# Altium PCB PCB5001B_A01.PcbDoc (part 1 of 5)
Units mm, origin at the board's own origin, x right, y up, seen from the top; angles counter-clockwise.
Board outline 115 x 60 mm, 6 copper layers (Top Layer, GND Layer 2, Signal Layer 3, Signal Layer 4, VCC Layer 5, Bottom Layer), stack 1.555 mm thick; 370 components, 274 nets, 1305 pads, 1129 vias.
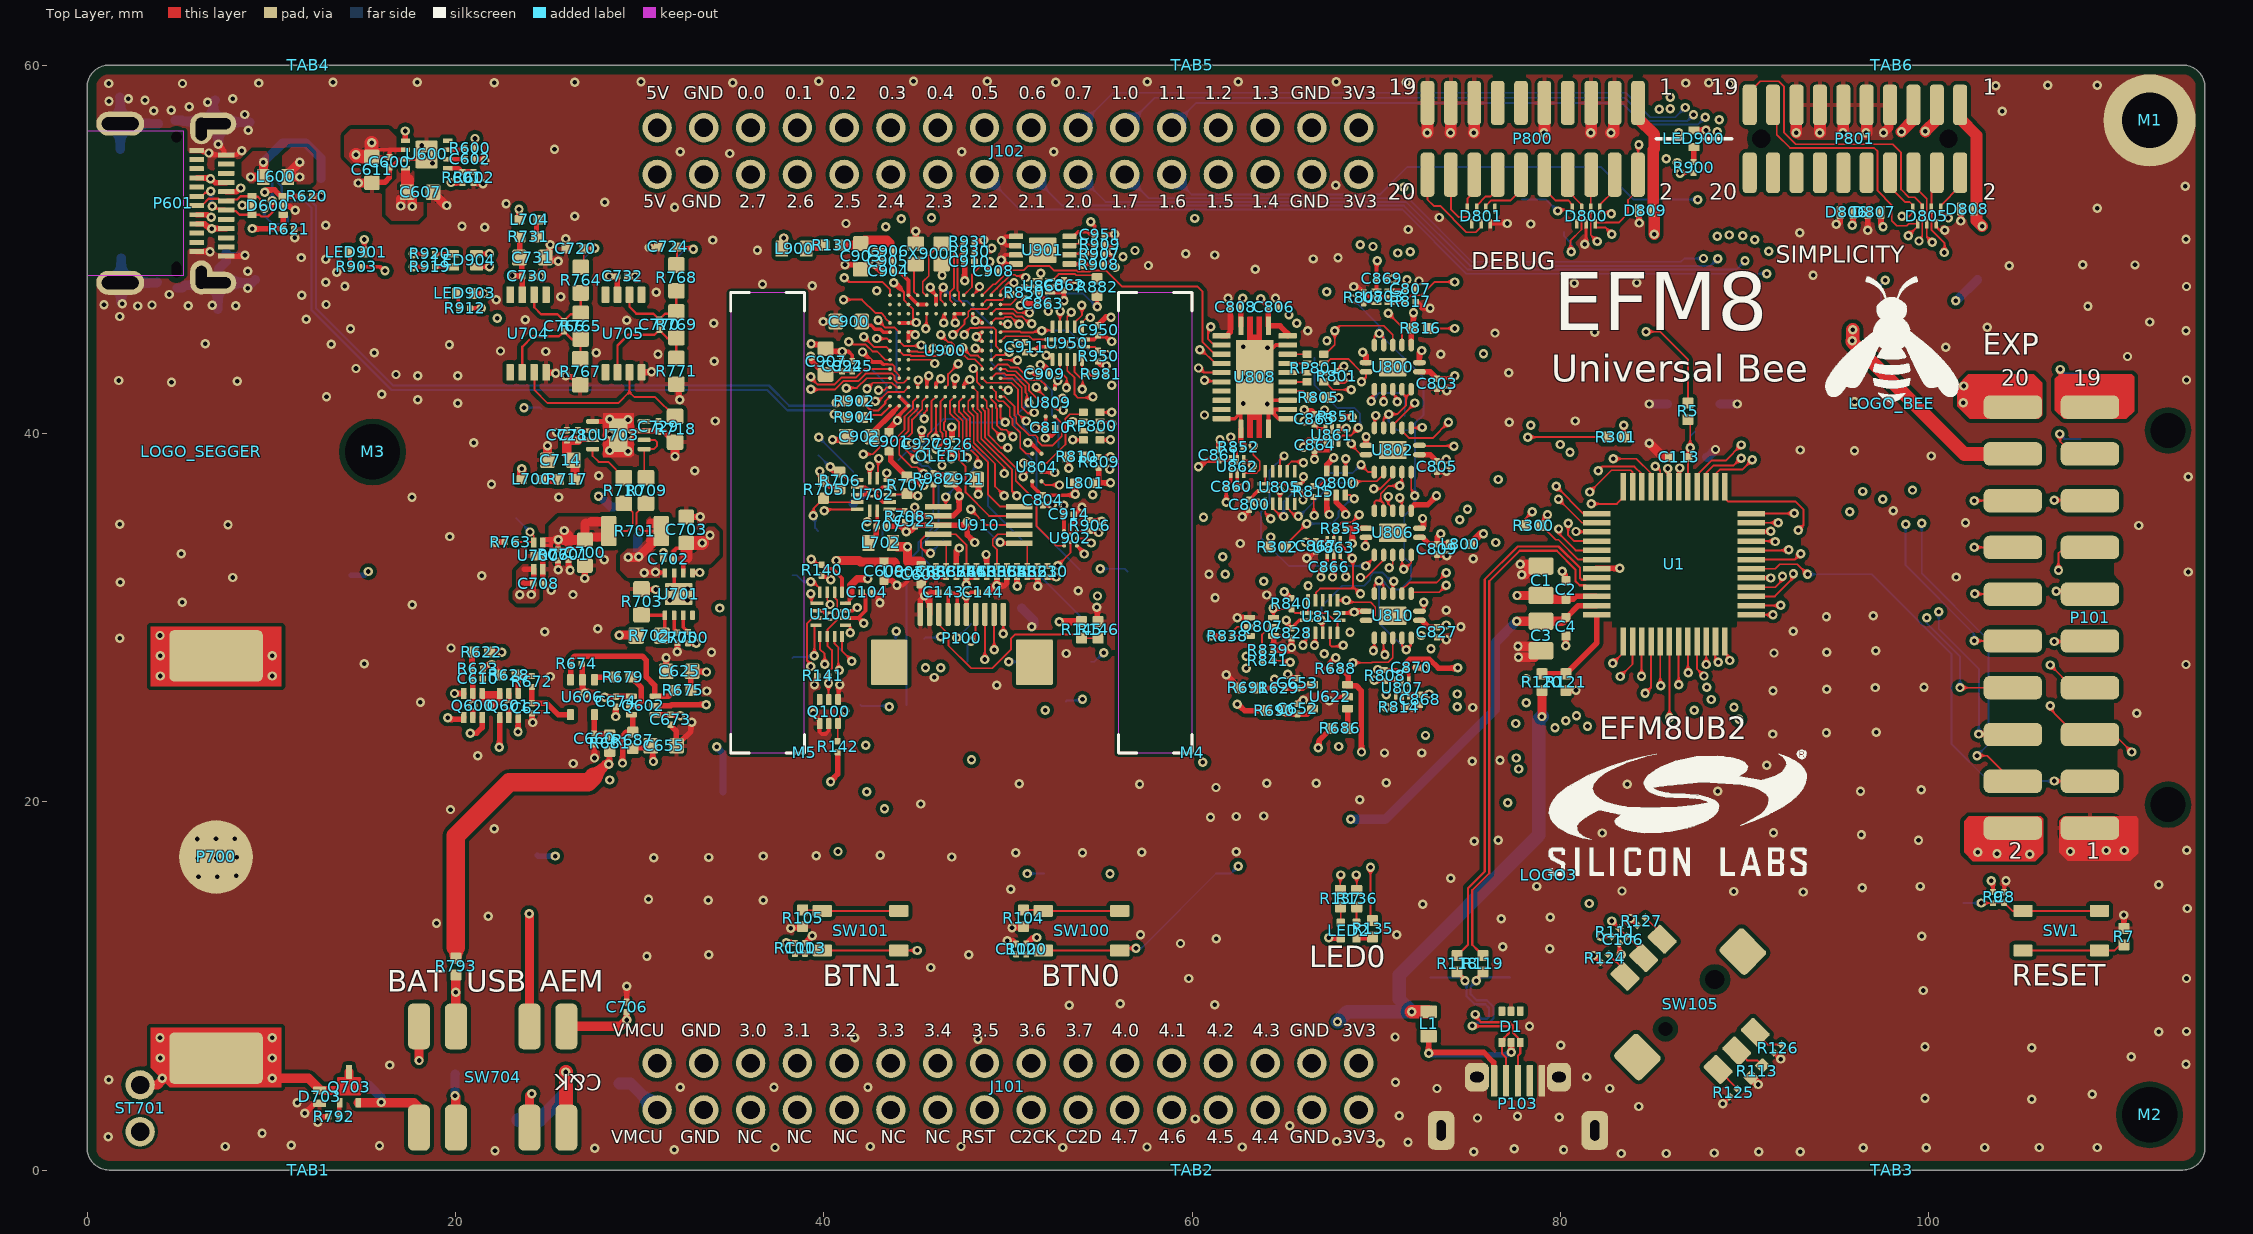
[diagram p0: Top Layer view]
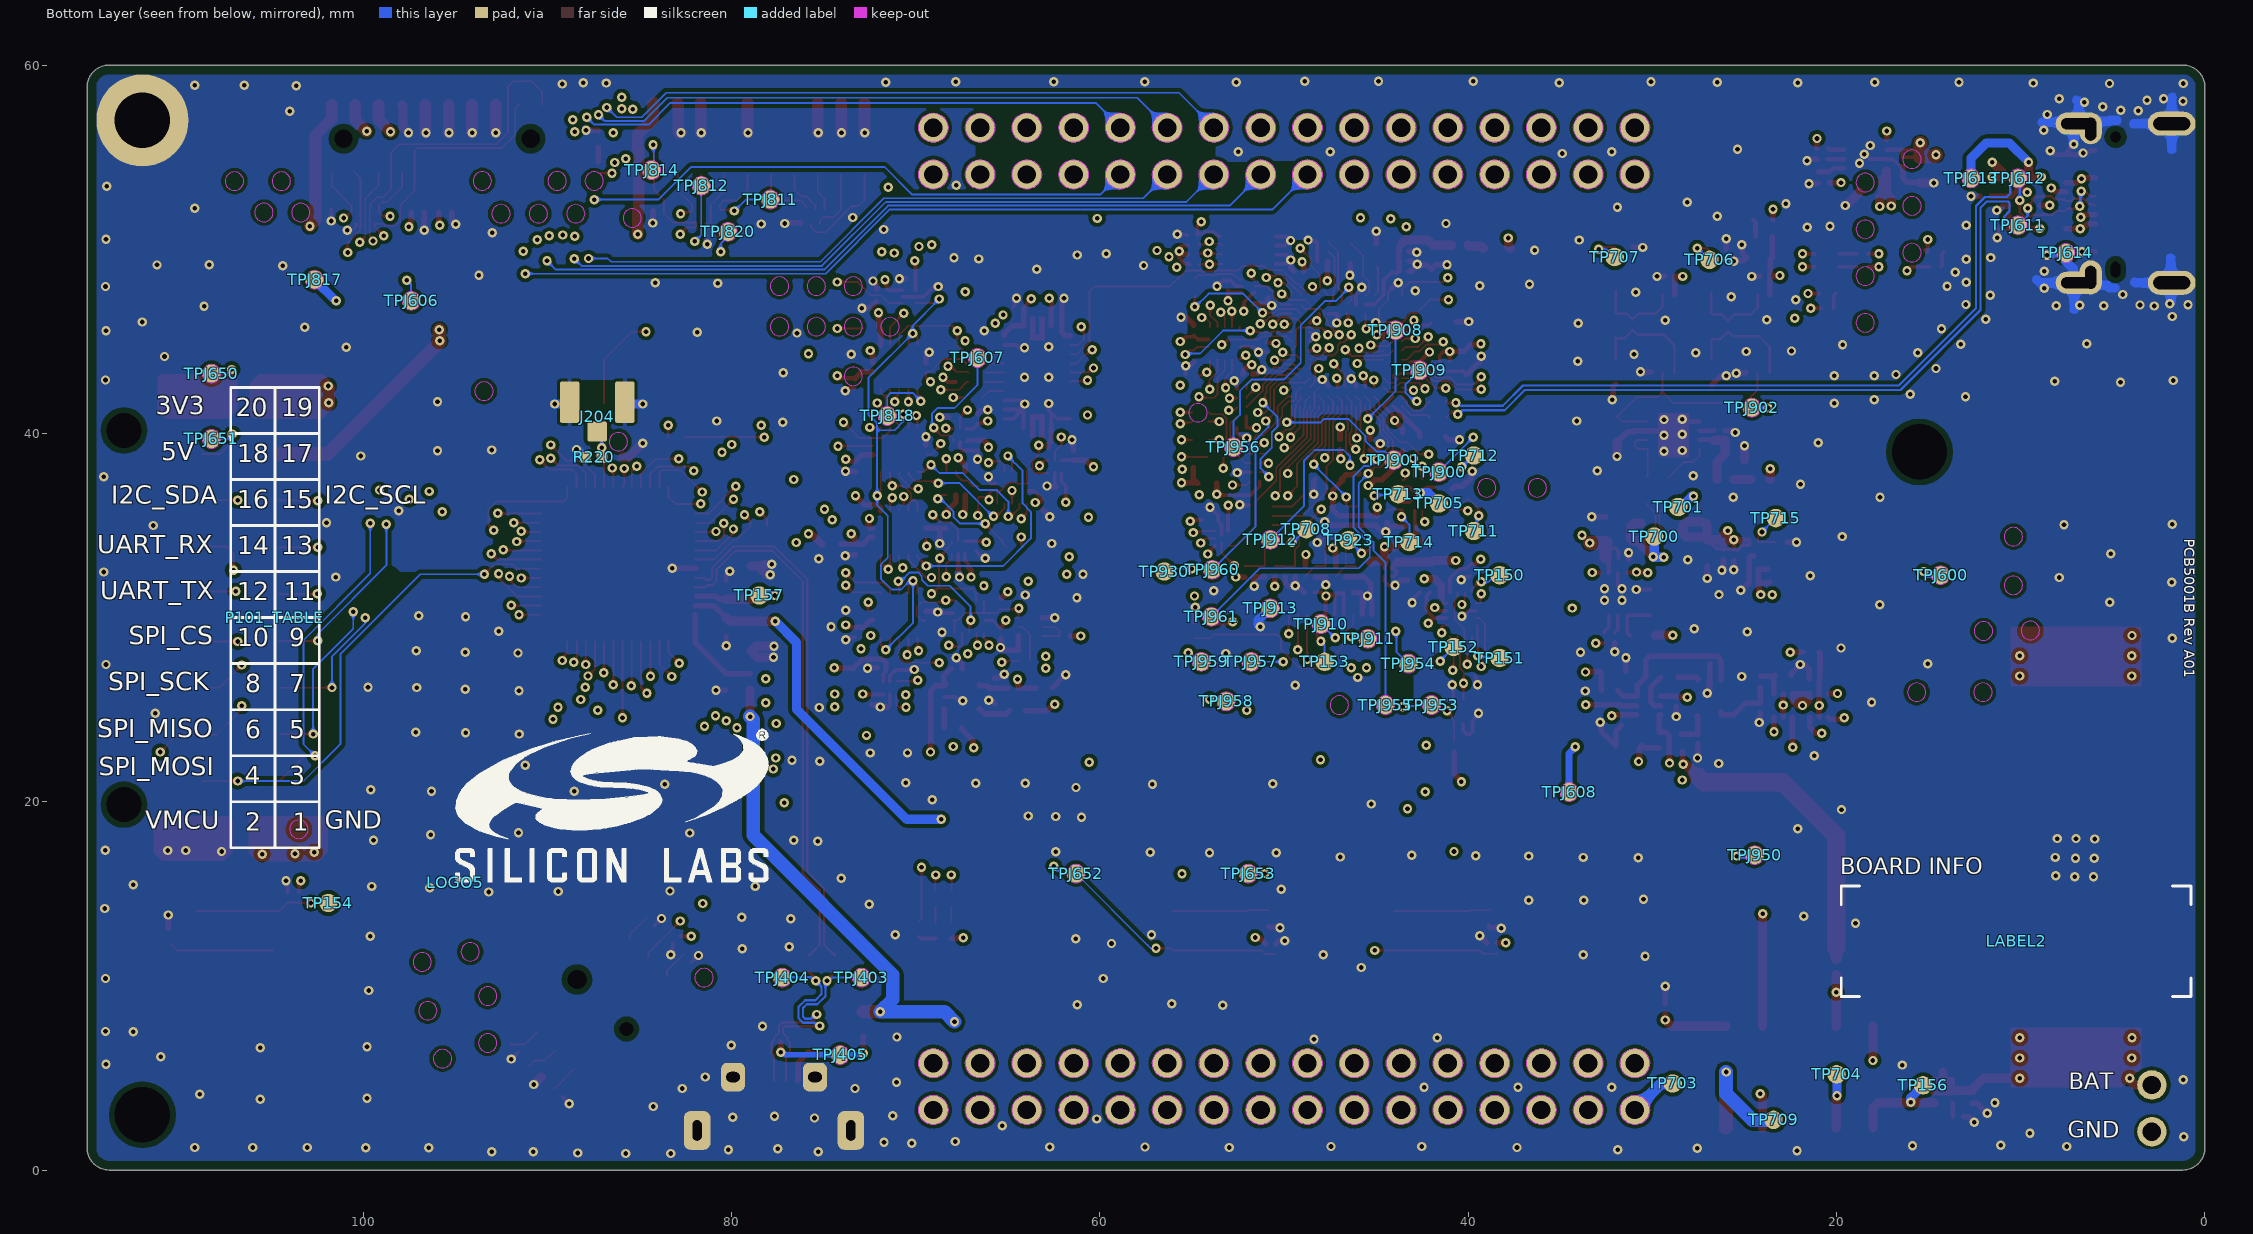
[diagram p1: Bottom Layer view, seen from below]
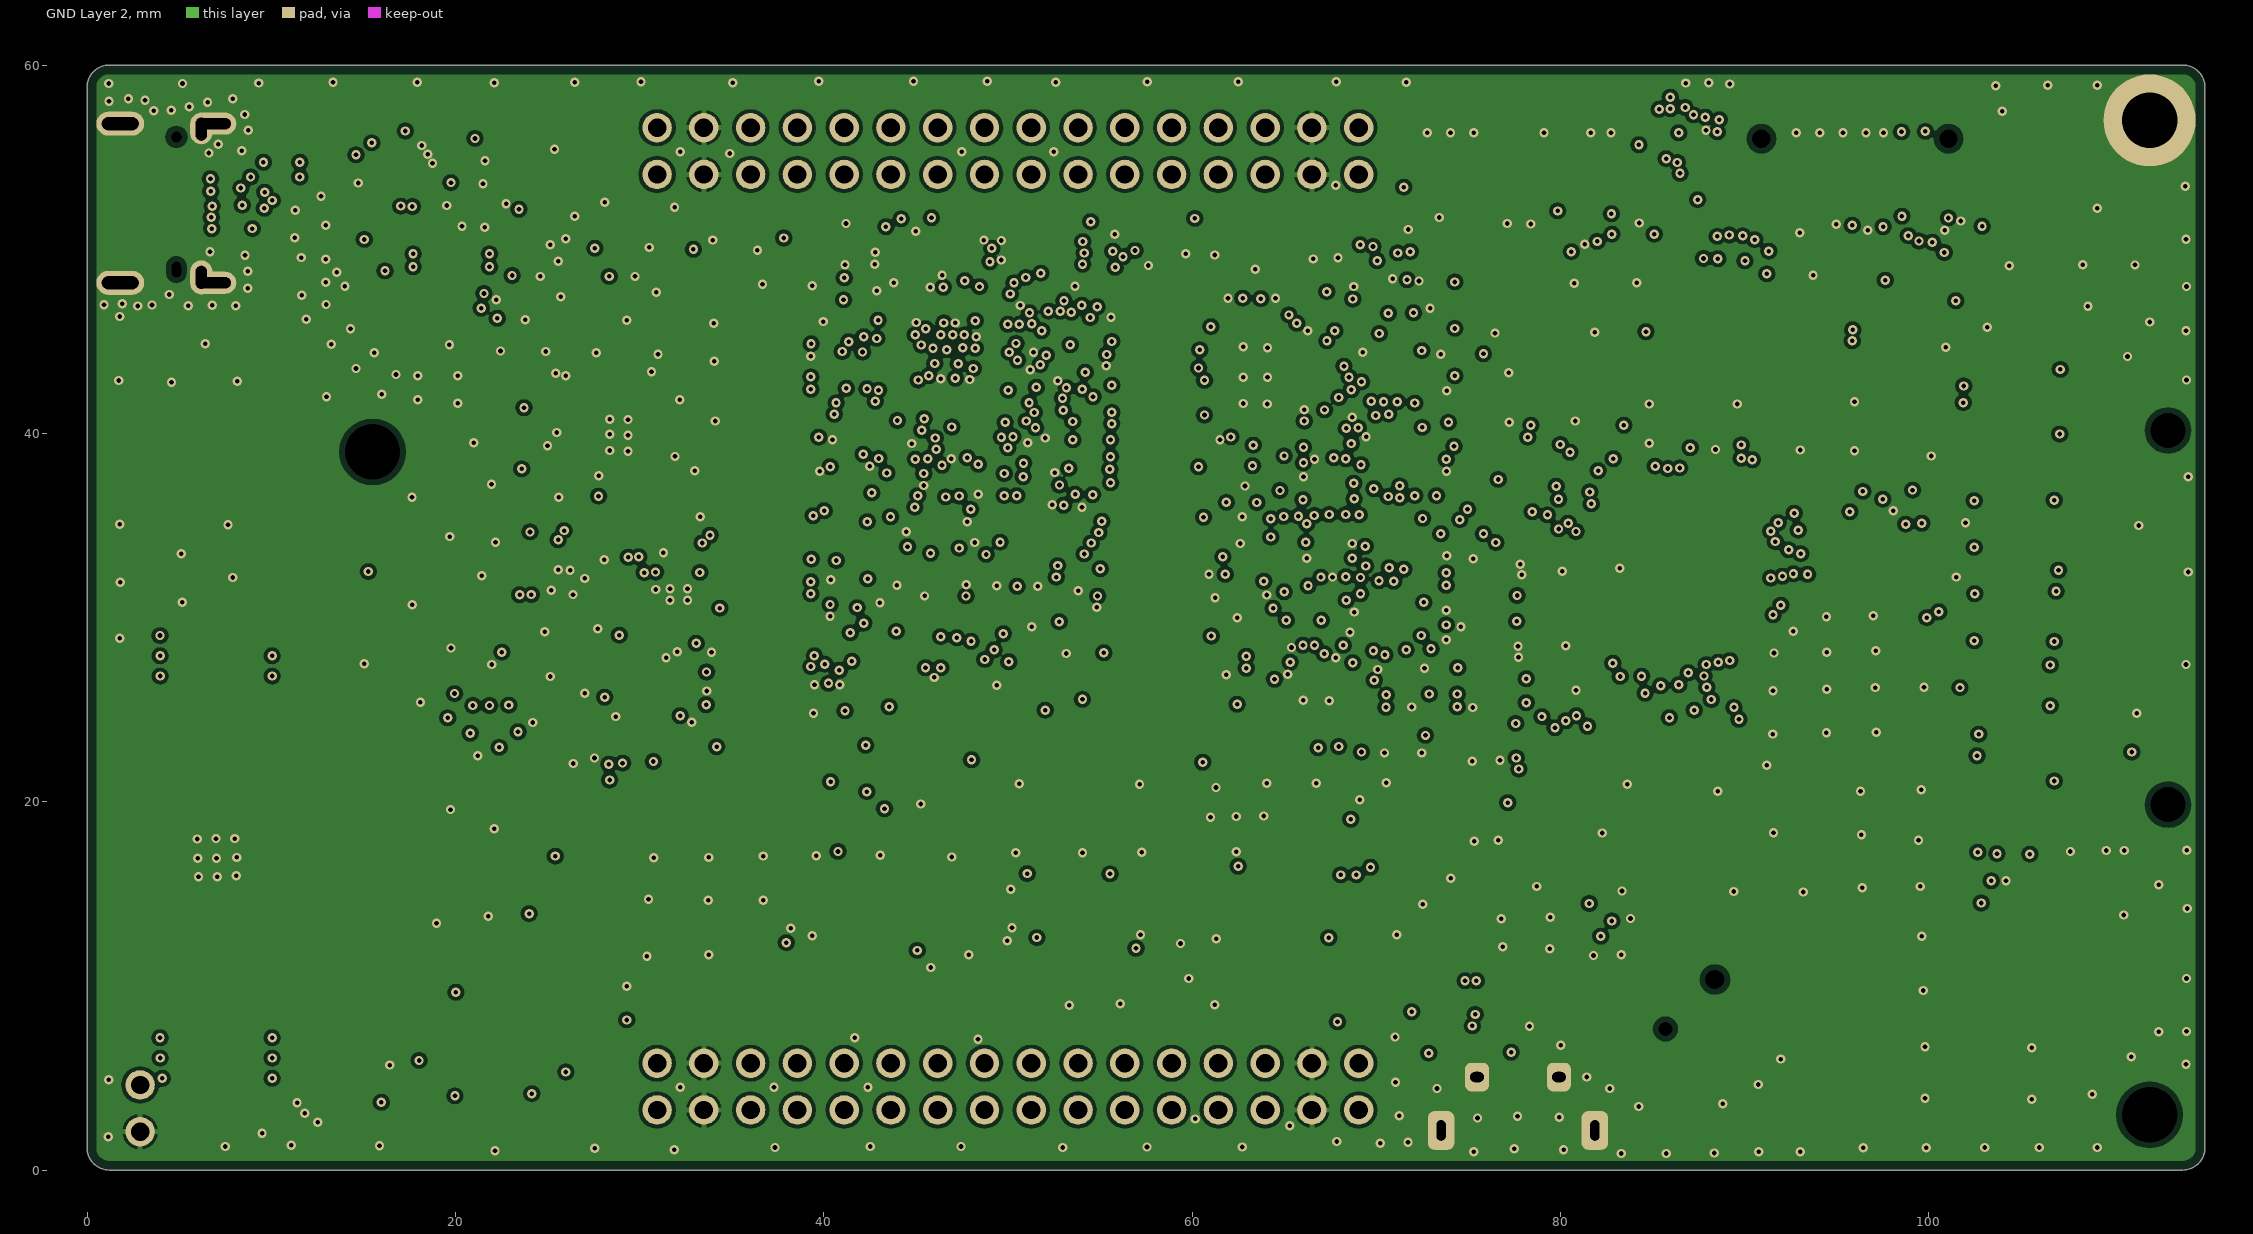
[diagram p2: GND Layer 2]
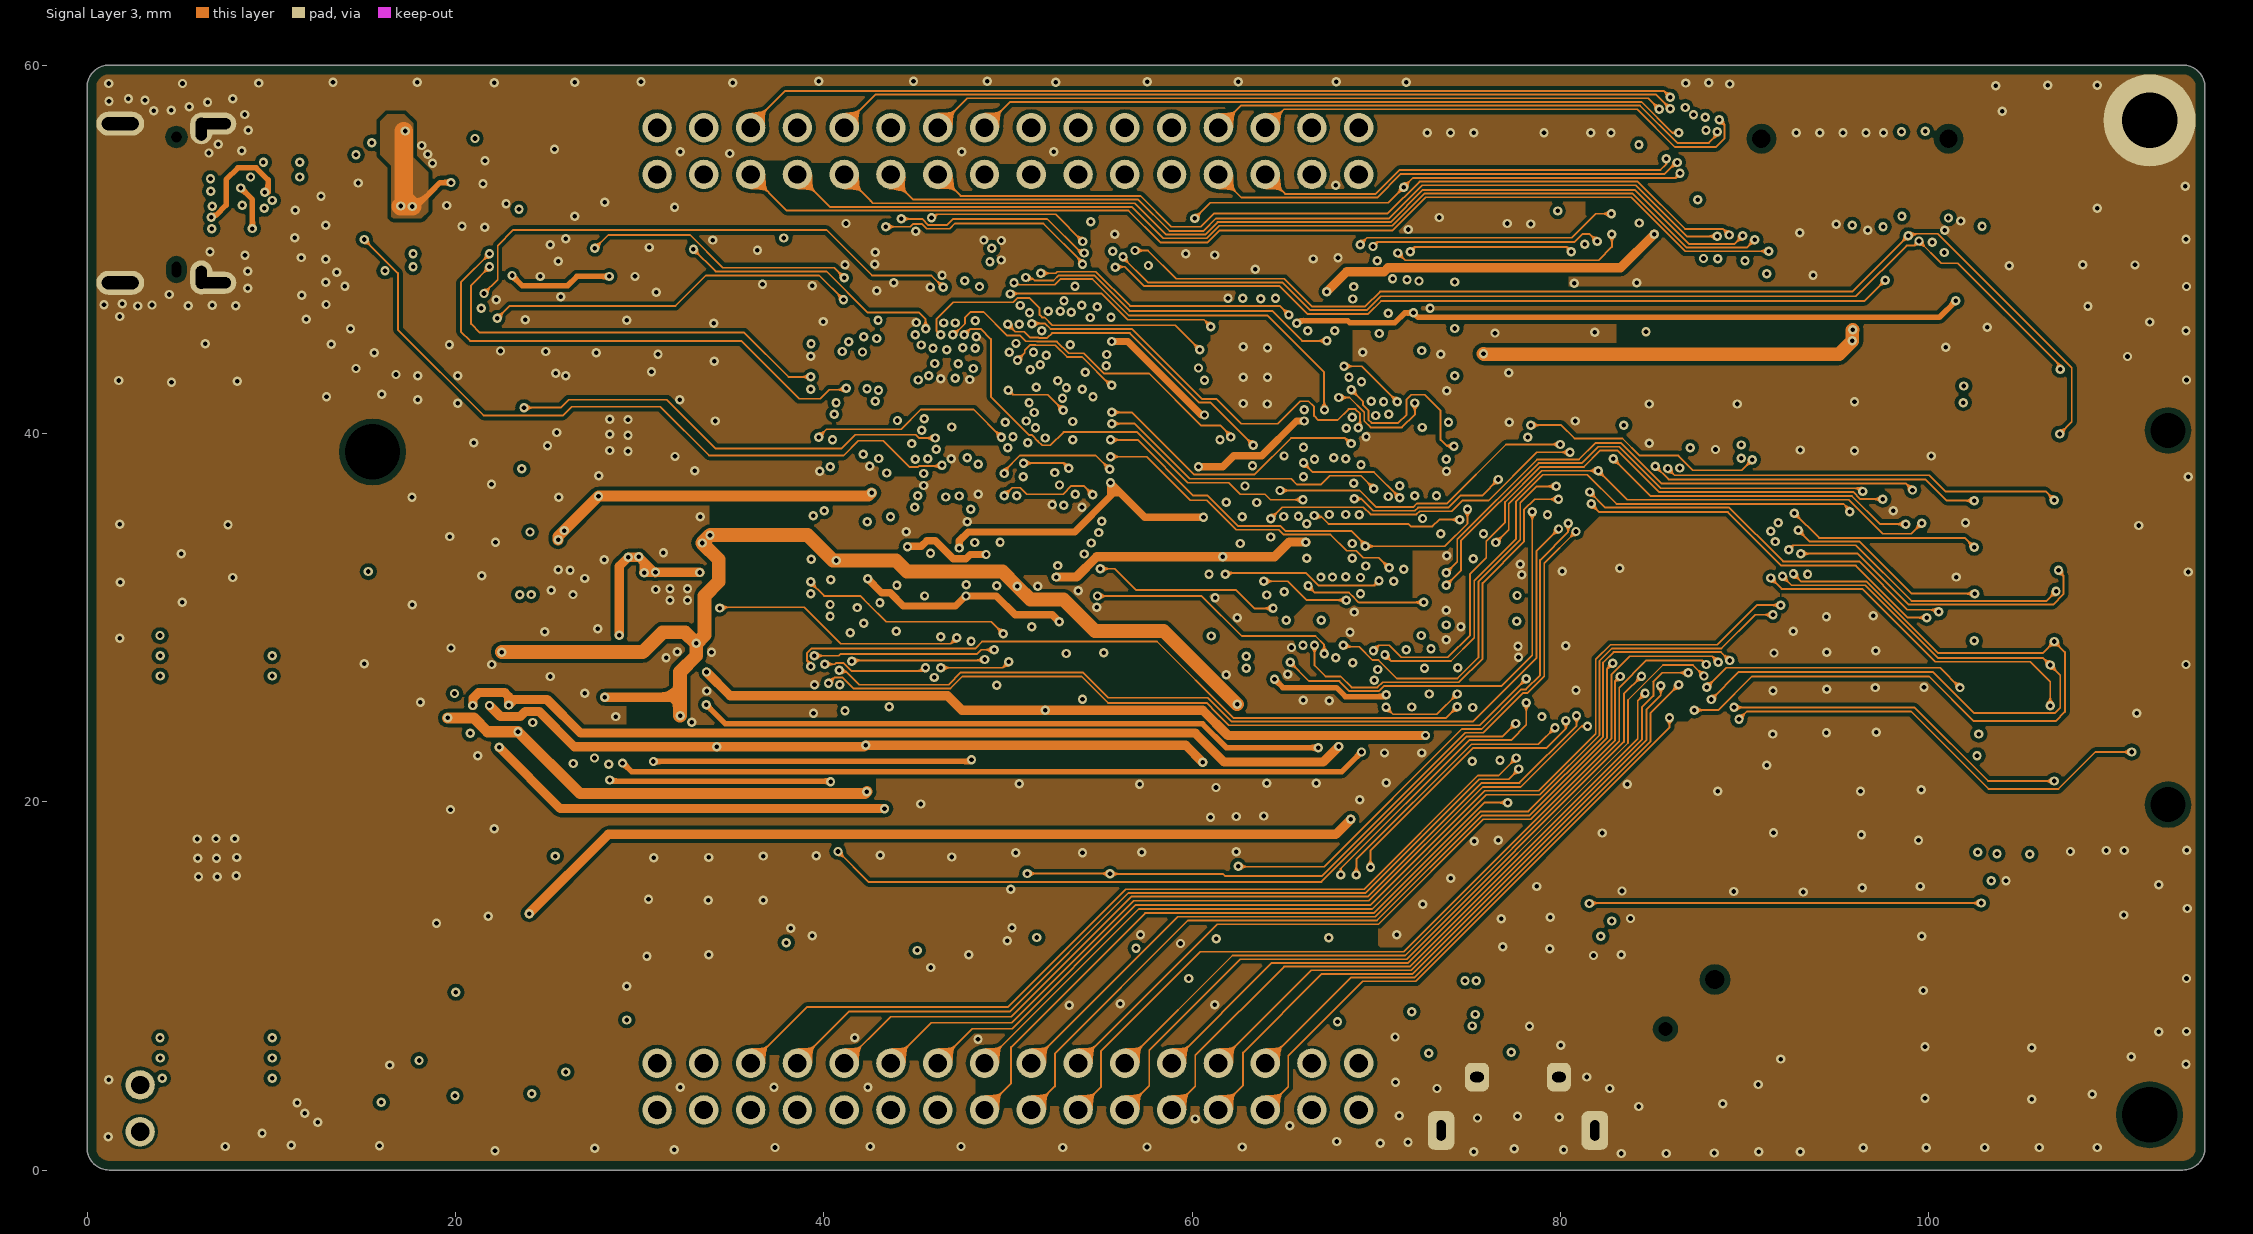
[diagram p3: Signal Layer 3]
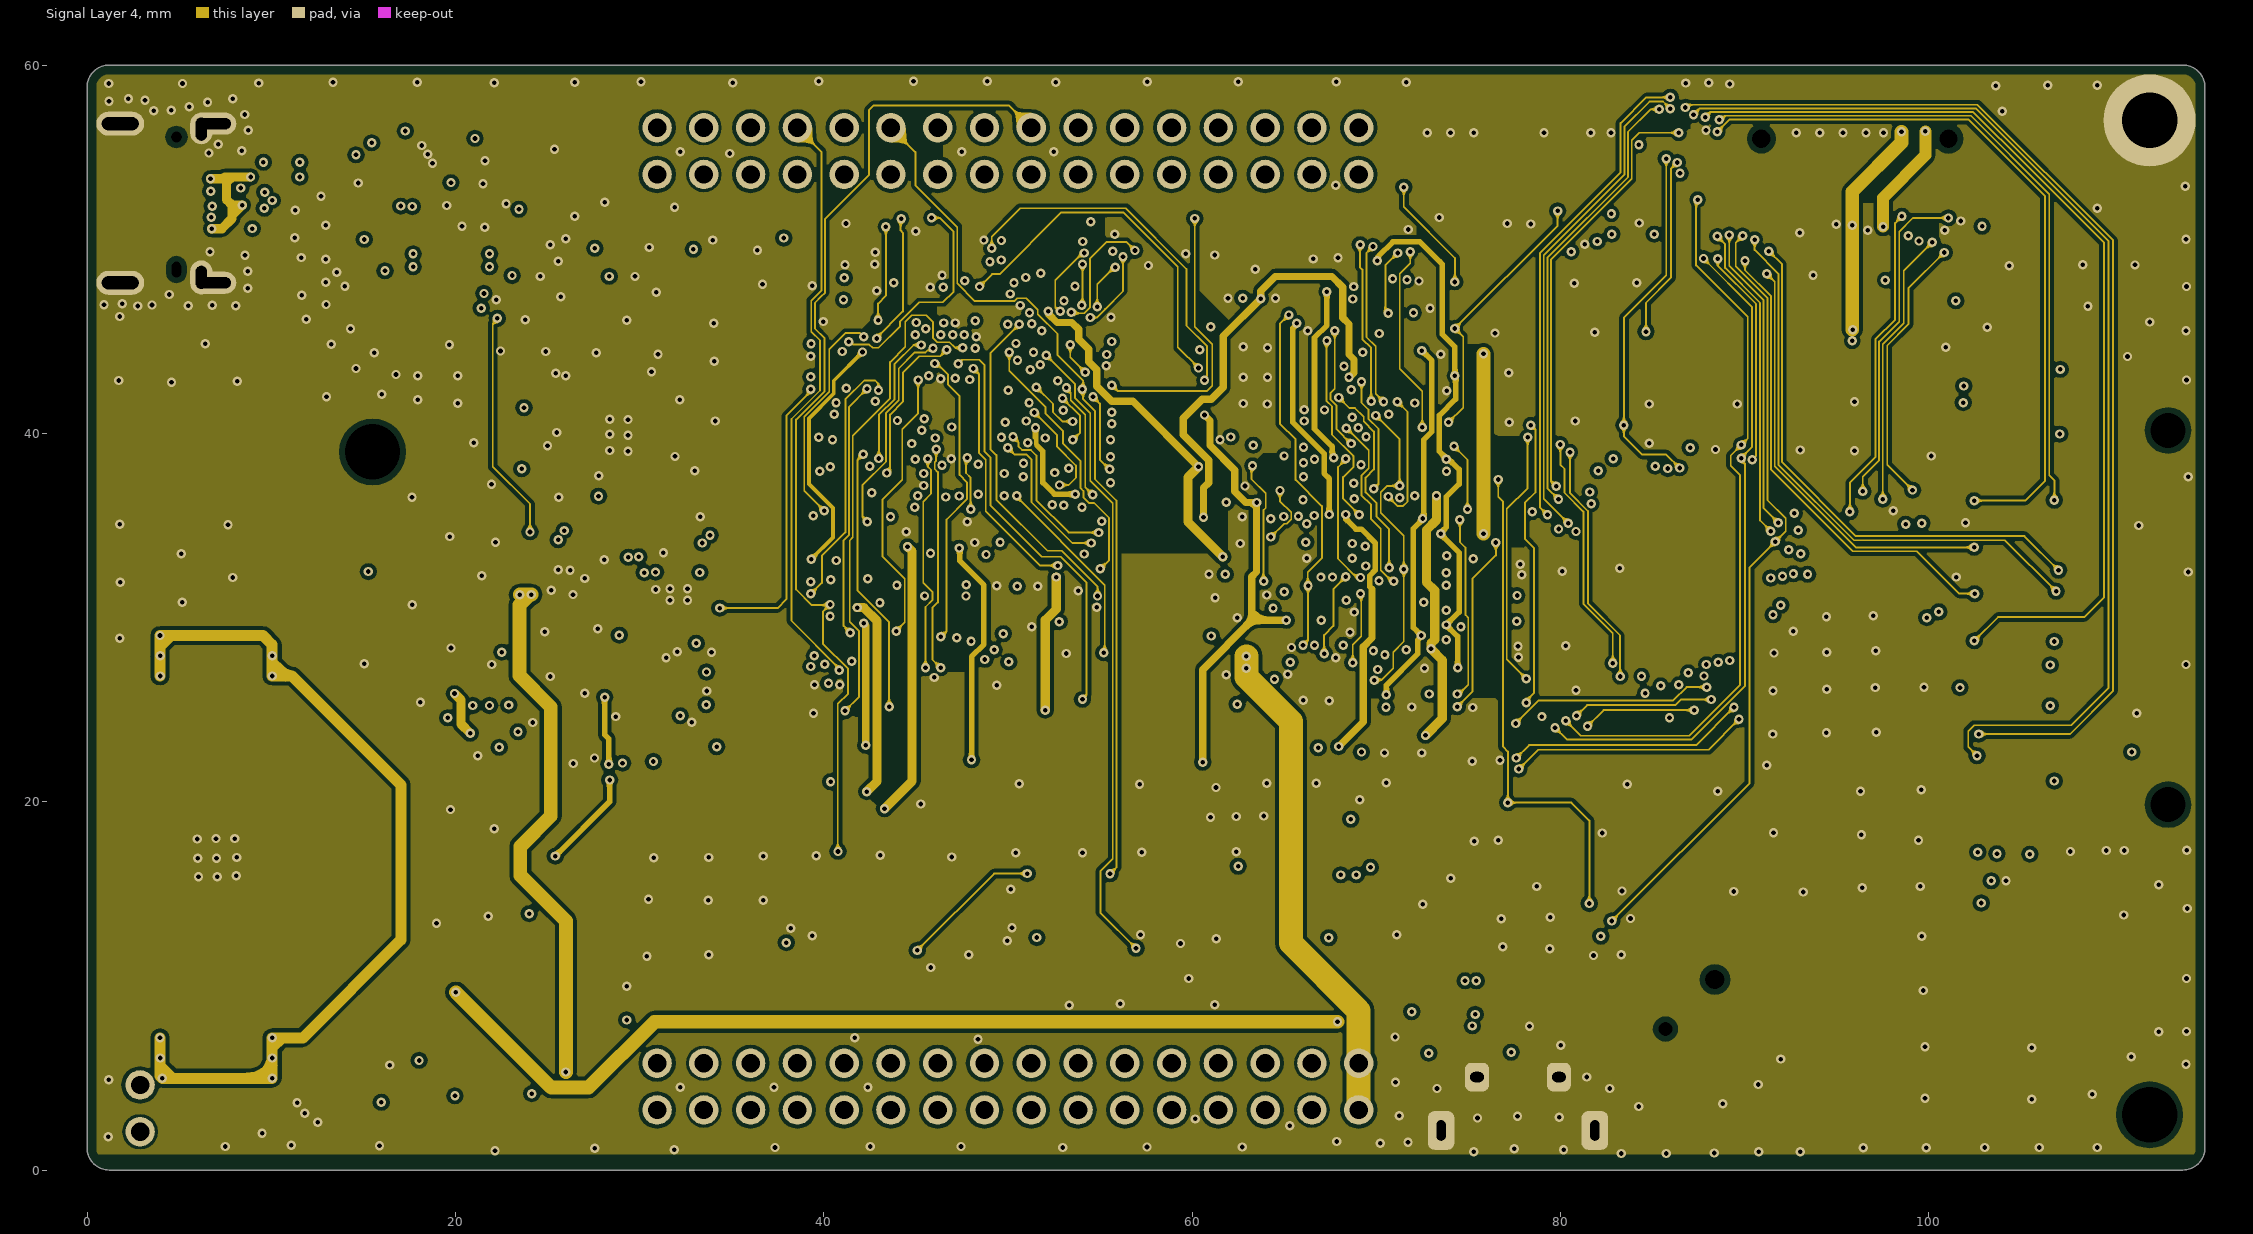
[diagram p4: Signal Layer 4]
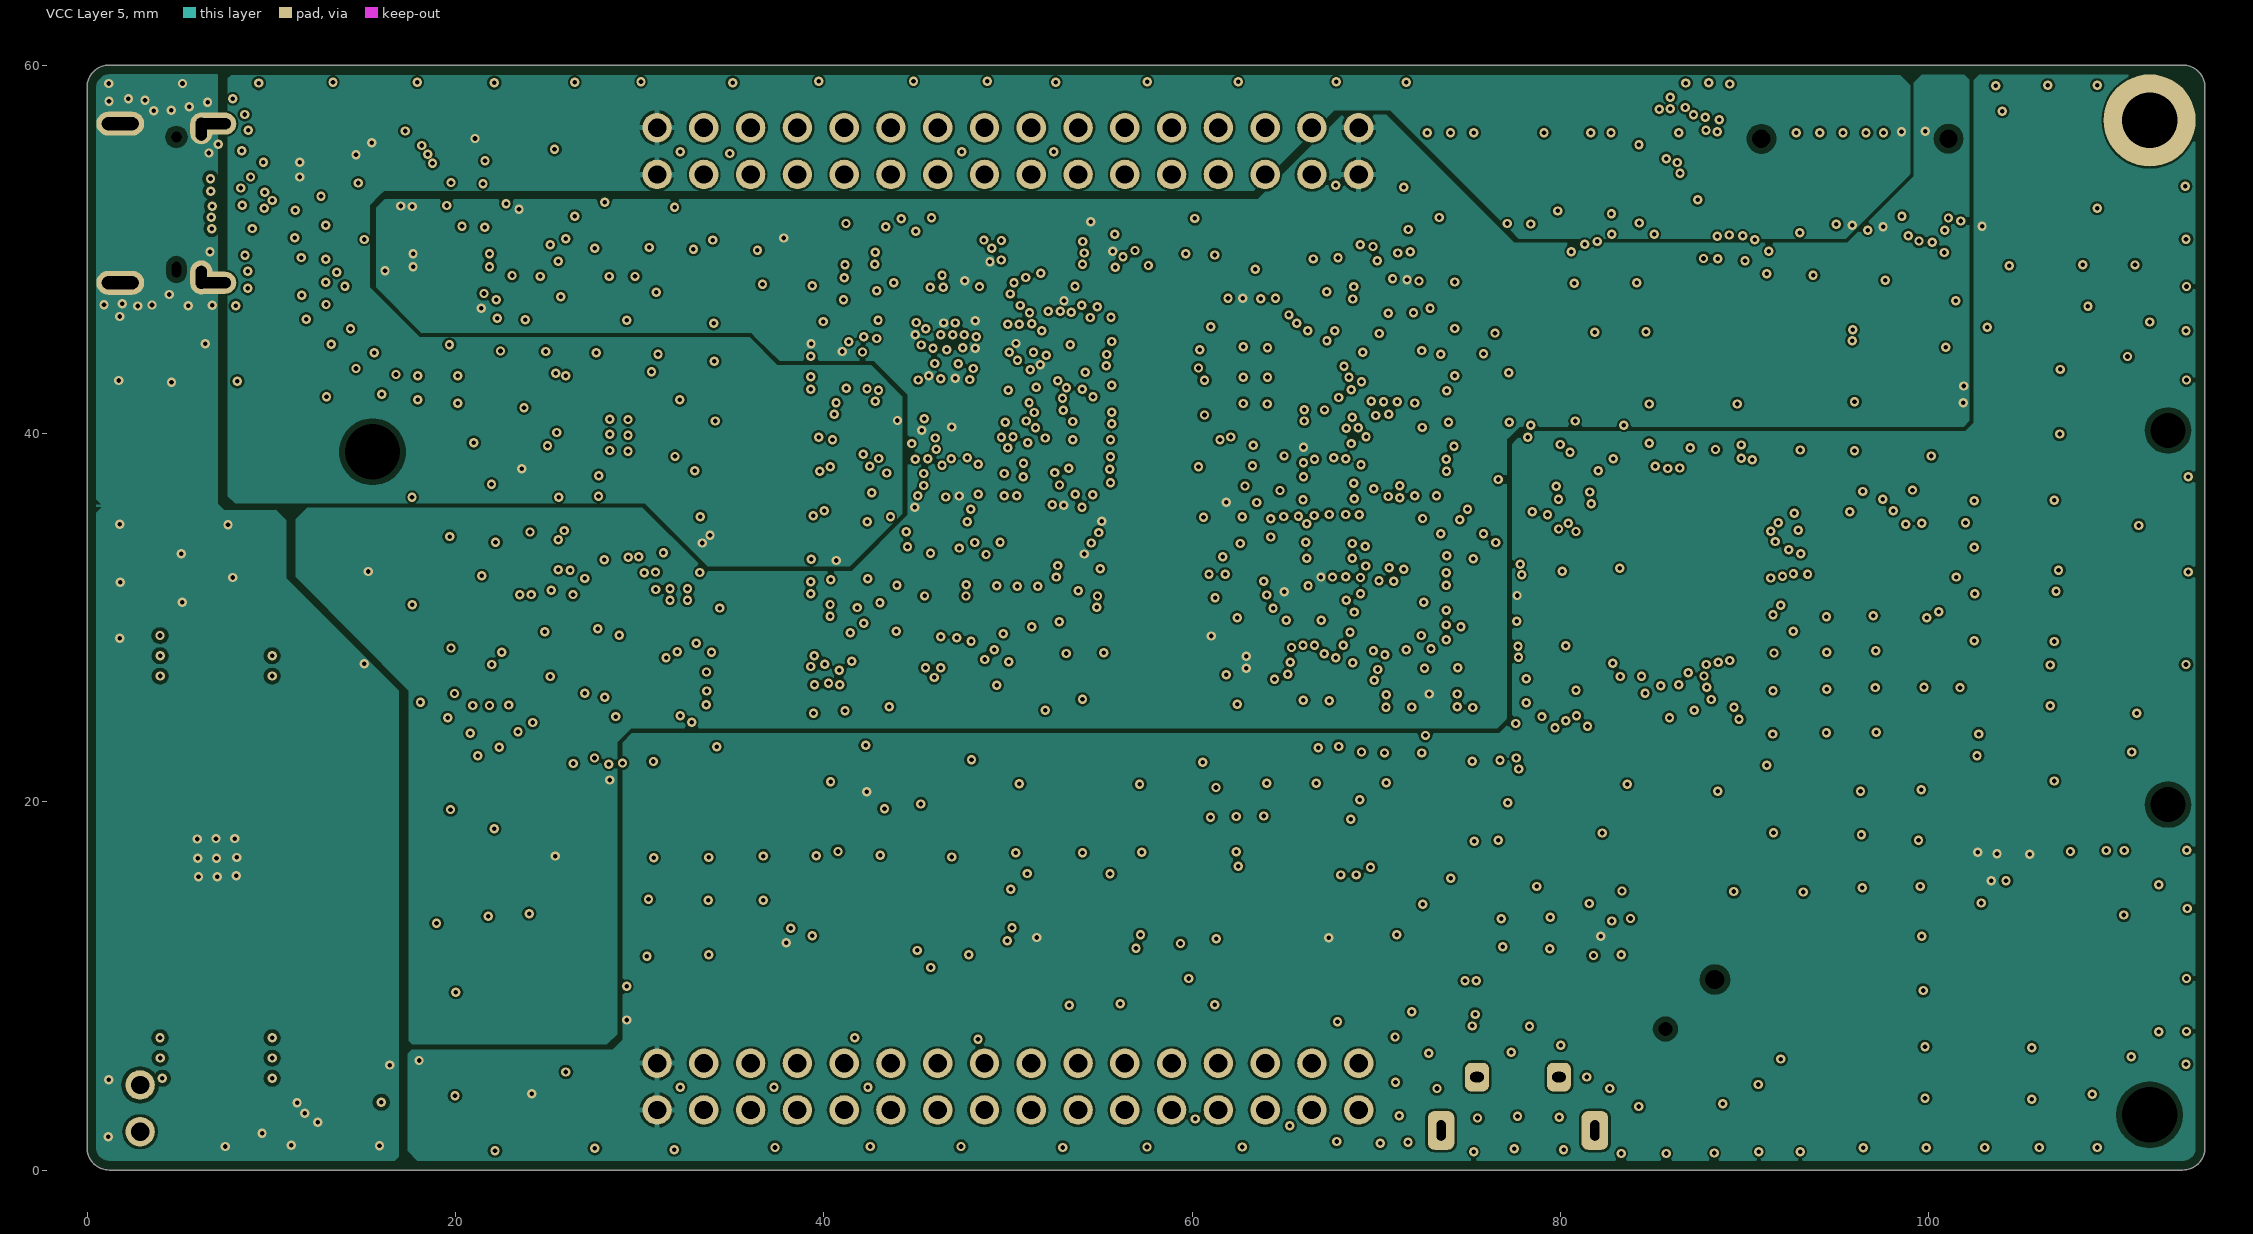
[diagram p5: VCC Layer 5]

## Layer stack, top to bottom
Top Solder: solder mask 0.03, Solder Resist, Dk 3.5
Top Layer: signal copper 0.035
Dielectric 1: prepreg 0.1, FR-4, Dk 4.2
GND Layer 2: signal copper 0.035
Dielectric 2: core 0.46, Core-009, Dk 4.2
Signal Layer 3: signal copper 0.035
Dielectric 3: prepreg 0.225, PP-006, Dk 4.2
Signal Layer 4: signal copper 0.035
Dielectric 4: core 0.46, Core-009, Dk 4.2
VCC Layer 5: signal copper 0.035
Dielectric  5: prepreg 0.1, FR-4, Dk 4.2
Bottom Layer: signal copper 0.035
Bottom Solder: solder mask 0.03, Solder Resist, Dk 3.5

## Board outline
0,1.2 0,58.8 cw(c1.2,58.8) 1.2,60 113.8,60 cw(c113.8,58.8) 115,58.8 115,1.2 cw(c113.8,1.2) 113.8,0 1.2,0 cw(c1.2,1.2)

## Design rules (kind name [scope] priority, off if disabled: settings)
BoardOutlineClearance BoardOutlineClearance_IGNORE_USB [HasFootprint('FCI_10137065_USB-C_RCPT') and IsKeepOut] p1: gap=0.5 ignorepadtopadclearanceinfootprint=FALSE except(0: Region-OutlineEdge Region-CavityEdge Region-CutoutEdge Region-SplitBarrior Region-SplitContinuation; 0.26: Arc-CutoutEdge Track-CutoutEdge SMDPad-CutoutEdge THPad-CutoutEdge Via-CutoutEdge Fill-CutoutEdge Poly-CutoutEdge Text-CutoutEdge; 0.4: THPad-OutlineEdge)
BoardOutlineClearance [Not HasFootprint('TAB50.5_T1.6_W2.4') or not HasFootprint('FCI_10137065_USB-C_RCPT')] p2: gap=0.5 ignorepadtopadclearanceinfootprint=FALSE except(0.26: Arc-CutoutEdge Track-CutoutEdge SMDPad-CutoutEdge THPad-CutoutEdge Via-CutoutEdge Fill-CutoutEdge Poly-CutoutEdge Region-CutoutEdge Text-CutoutEdge; 0.4: THPad-OutlineEdge)
Clearance Clearance_NPL [(ObjectKind = 'Pad') And (Layer = 'MultiLayer') And (PadIsPlated = 'False')] p1: gap=0.3 ignorepadtopadclearanceinfootprint=FALSE
Clearance Clearance_Polygon_GND [InNet('GND') and InPolygon] p2: gap=0.2 ignorepadtopadclearanceinfootprint=FALSE
Clearance Clearance_Polygon_General [InPolygon] p3: gap=0.125 ignorepadtopadclearanceinfootprint=FALSE
Clearance Clearance_Via_Track [IsVia vs IsTrack] p4: gap=0.089 ignorepadtopadclearanceinfootprint=FALSE except(0: Arc-Hole Track-Hole SMDPad-Hole THPad-Hole Via-Hole Fill-Hole Poly-Hole Region-Hole Text-Hole)
Clearance [All] p5: gap=0.1 ignorepadtopadclearanceinfootprint=FALSE
ComponentClearance ComponentClearance_IGNORE [HasFootprint('TESTJIGG_PCB4002_M14') OR HasFootprint('TAB50.5_T1.6_W2.4') OR HasFootprint('TP_6.0X6.0_MILLOUT_5.0X5.0_TH') Or InComponent('M1')] p1: gap=0 collisioncheckmode=3 verticalgap=0 showdistances=FALSE
ComponentClearance [All] p2: gap=0.2 collisioncheckmode=3 verticalgap=0.254 showdistances=FALSE
DiffPairsRouting DiffPairsRouting_90OHM [InDifferentialPair('USB90') or InDifferentialPair('USB90_1') or InDifferentialPair('USB90ohm') or InDifferentialPair('USB90ohm_1')] p1: maxlimit=0.254 minlimit=0.12 mostfreqgap=0.254 toplayer_maxgap=0.12 toplayer_prefgap=0.12 toplayer_minwidth=0.12 toplayer_maxwidth=0.12 toplayer_prefwidth=0.12 bottomlayer_maxgap=0.12 bottomlayer_prefgap=0.12 bottomlayer_minwidth=0.12 bottomlayer_maxwidth=0.12 bottomlayer_prefwidth=0.12 impedanceprofiledriven=TRUE impedanceprofileid={B4300C99-598D-4438-91CE-854F904B181D} impedanceprofilevalue=90.000000 maxuncoupledlength=50
DiffPairsRouting DiffPairsRouting_90OHM_1 [InDifferentialPair('USB_90ohm') or InDifferentialPair('USB1_90ohm')] p2: maxlimit=0.254 minlimit=0.12 mostfreqgap=0.254 toplayer_maxgap=0.12 toplayer_prefgap=0.12 toplayer_minwidth=0.12 toplayer_maxwidth=0.12 toplayer_prefwidth=0.12 bottomlayer_maxgap=0.12 bottomlayer_prefgap=0.12 bottomlayer_minwidth=0.12 bottomlayer_maxwidth=0.12 bottomlayer_prefwidth=0.12 impedanceprofiledriven=TRUE impedanceprofileid={B4300C99-598D-4438-91CE-854F904B181D} impedanceprofilevalue=90.000000 maxuncoupledlength=50
HoleSize [All] p1: absolutevalues=TRUE maxlimit=10 minlimit=0.1 maxpercent=80.000 minpercent=20.000
HoleToHoleClearance HoleToHoleClearance_general [Not InComponent('P601')] p1: gap=0.254 allowstackedmicrovias=TRUE
MinimumSolderMaskSliver MinimumSolderMaskSliver_IGNORE [InComponent('LOGO*') vs InComponent('LOGO*')] p1: minsoldermaskwidth=0
MinimumSolderMaskSliver [All] p2: minsoldermaskwidth=0.1
PolygonConnect PolygonConnect_Direct_Connect [InComponent('M1') or InComponent('J1') or InComponent('P700') or InComponent('P601') or InComponent('P103')] p1: connectstyle=Direct reliefconductorwidth=0.33 reliefentries=4 polygonreliefangle="90 Angle" airgapwidth=0.152
PolygonConnect PolygonConnect_IGNORE_GND_FILL [IsThruPin vs InNet('GND') and not OnLayer('GND Layer 2')] p2: connectstyle=NoConnect reliefconductorwidth=0.3 reliefentries=4 polygonreliefangle="90 Angle" airgapwidth=0.15
PolygonConnect PolygonConnect_general [All] p3: thpad.connectstyle=Relief thpad.reliefconductorwidth=0.3 thpad.reliefentries=4 thpad.polygonreliefangle="90 Angle" thpad.airgapwidth=0.15 smdpad.connectstyle=Relief smdpad.reliefconductorwidth=0.25 smdpad.reliefentries=4 smdpad.polygonreliefangle="90 Angle" smdpad.airgapwidth=0.15 via.connectstyle=Direct via.reliefconductorwidth=0.33 via.reliefentries=4 via.polygonreliefangle="90 Angle" via.airgapwidth=0.127
RoutingVias RoutingVias_Through [InDrillLayerPair('Top Layer - Bottom Layer')] p1: holewidth=0.25 width=0.508 viastyle="Through Hole" minholewidth=0.25 minwidth=0.508 maxholewidth=1 maxwidth=1.5 useviatemplates=TRUE viatemplateguid#1={89E5EF08-91F7-4BC1-BF72-0CDB5ADAF91B} viatemplatename#1=v51h25m0mx0(Tol8-8)
ShortCircuit ShortCircuit_General [All] p1: allowed=FALSE
SilkToSilkClearance [All] p1: silktosilkclearance=0.102
SilkToSolderMaskClearance [IsPad] p1: minsilkscreentomaskgap=0.102 clearancetoexposedcopper=TRUE
SolderMaskExpansion [All] p1: expansion=0.05 istentingtop=FALSE
UnRoutedNet [All] p1: checkbadconnections=TRUE
Width [All] p1: maxlimit=5.08 minlimit=0.1 preferedwidth=0.1 minimp=50.000000 maximp=50.000000 favimp=50.000000
21 further rules are at their usual default settings.

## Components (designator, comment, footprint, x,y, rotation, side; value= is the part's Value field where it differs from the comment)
C1 "10U" C0805 78.95,32 r90 top
C2 "100N" C0402 80.3,31.5 r90 top
C3 "10U" C0805 78.95,29 r270 top
C4 "100N" C0402 80.3,29.5 r270 top
C8 "100N" C0201 104.1,14.8 r90 top
C102 "1N" C0201 50.45,12 r90 top
C103 "1N" C0201 38.986,12.031 r90 top
C104 "100N" C0201 42.348,31.374 r0 top
C106 "1N" C0201 83.4,12.5 r225 top
C113 "100N" C0402 86.425,38.7 r180 top
C143 "100N" C0201 46.499,31.364 r180 top
C144 "100N" C0201 48.625,31.368 r0 top
C600 "100N" C0201 16.417,54.726 r270 top
C602 "33N" C0201 20.782,54.897 r0 top
C607 "10U" C0603 18.082,53.097 r0 top
C608 "1U" C0402 45.3,32.325 r270 top
C609 "1U" C0402 43.275,32.525 r270 top
C610 "1N" C0201 21.2,26.675 r0 top
C611 "10U" C0603 15.465,54.314 r270 top
C621 "100N" C0201 24.15,25.075 r270 top
C625 "10U" C0603 32.148,27.08 r180 top
C632 "10N" C0201 51.05,32.5 r270 top
C635 "10N" C0201 49.4,32.5 r270 top
C638 "10N" C0201 46.1,32.5 r270 top
C641 "10N" C0201 47.75,32.5 r270 top
C652 "100N" C0201 65.725,25.036 r90 top
C653 "100N" C0201 65.72,26.44 r90 top
C655 "10U" C0603 31.304,23.036 r0 top
C660 "100N" C0201 27.537,23.41 r270 top
C673 "100N" C0201 31.675,24.45 r270 top
C674 "100N" C0201 28.713,25.422 r270 top
C700 "10U" C0603 27.033,33.525 r270 top
C701 "100N" C0201 26.134,33.412 r270 top
C702 "100N" C0201 31.57,33.171 r180 top
C703 "10U" C0603 32.535,34.761 r90 top
C705 "33N" C0201 32.05,28.904 r270 top
C706 "100N" C0201 29.3,8.85 r90 top
C707 "100N" C0201 43.15,34.95 r0 top
C708 "100N" C0201 24.5,31.85 r0 top
C710 "100N" C0201 26.65,39.9 r90 top
C714 "10U" C0603 25.7,38.55 r180 top
C720 "1N" C0402 26.5,50.025 r180 top
C724 "1N" C0402 31.525,50.125 r180 top
C728 "100N" C0201 26.05,39.9 r90 top
C729 "2N2" C0201 31.025,40.375 r270 top
C730 "100N" C0201 23.9,48.525 r0 top
C731 "10U" C0603 24.175,49.55 r0 top
C732 "100N" C0201 29.05,48.525 r0 top
C766 "10P" C0201 25.9,45.825 r270 top
C770 "10P" C0201 31.075,45.9 r270 top
C800 "100N" C0201 63.1,36.125 r270 top
C803 "100N" C0201 73.3,42.7 r270 top
C804 "100N" C0201 51.9,36.375 r270 top
C805 "100N" C0201 73.3,38.2 r270 top
C806 "100N" C0201 64.45,46.85 r0 top
C807 "100N" C0201 71.85,47.825 r0 top
C808 "100N" C0201 62.35,46.85 r180 top
C809 "100N" C0201 73.3,33.7 r270 top
C810 "100N" C0201 52.3,40.3 r0 top
C827 "100N" C0201 73.3,29.2 r270 top
C828 "100N" C0201 65.4,29.15 r270 top
C860 "100N" C0201 62.125,37.1 r0 top
C861 "100N" C0201 61.45,38.825 r90 top
C862 "100N" C0201 53.05,48.05 r90 top
C863 "100N" C0201 51.9,47.05 r180 top
C864 "100N" C0201 66.65,39.35 r270 top
C865 "100N" C0201 66.65,40.775 r90 top
C866 "100N" C0201 67.425,32.725 r0 top
C867 "100N" C0201 66.725,33.875 r270 top
C868 "100N" C0201 72.376,25.539 r270 top
C869 "100N" C0201 70.294,48.403 r0 top
C870 "100N" C0201 71.9,27.284 r0 top
C900 "1U" C0603 41.35,46.075 r180 top
C901 "1U" C0402 43.55,39.55 r270 top
C902 "4U7" C0603 41.925,39.825 r180 top
C903 "10U" C0603 42.006,49.615 r270 top
C904 "10N" C0201 43.498,48.802 r180 top
C905 "10N" C0201 43.485,49.352 r180 top
C906 "10N" C0201 43.498,49.896 r180 top
C907 "4U7" C0603 40.1,43.9 r270 top
C908 "100N" C0201 49.2,48.8 r0 top
C909 "100N" C0201 51.98,43.224 r180 top
C910 "100N" C0201 47.909,49.333 r0 top
C911 "100N" C0201 50.925,44.675 r270 top
C914 "100N" C0201 53.3,35.6 r0 top
C921 "4U7" C0603 47.6,37.5 r0 top
C922 "100N" C0201 44.95,35.225 r270 top
C924 "100N" C0201 41,43.65 r270 top
C925 "100N" C0201 41.55,43.65 r270 top
C926 "100N" C0201 46.975,39.4 r270 top
C927 "100N" C0201 45.325,39.4 r270 top
C950 "10N" C0201 54.9,45.6 r90 top
C951 "100N" C0201 54.997,50.778 r0 top
D1 "DT1446-04" SOT563_DIODES 77.325,7.775 r270 top
D600 "DT1446-04" SOT563_DIODES 9.797,52.374 r180 top
D703 "ESD" X2-DFN1006-2 12.625,3.975 r270 top
D800 "PUSB3AB6" DFN2111-7_M050_1.2X2.1_NXP 81.4,51.8 r270 top
D801 "PUSB3AB6" DFN2111-7_M050_1.2X2.1_NXP 75.7,51.8 r270 top
D805 "PUSB3AB6" DFN2111-7_M050_1.2X2.1_NXP 99.9,51.8 r270 top
D806 "ESD" X2-DFN1006-2 95.55,52 r180 top
D807 "ESD" X2-DFN1006-2 97.05,52 r180 top
D808 "ESD" X2-DFN1006-2 102.098,52.181 r180 top
D809 "ESD" X2-DFN1006-2 84.6,52.1 r180 top
J101 "HDR_M254_RING-2X16" HDR_M254_RING-2X16 50,4.532 r0 top
J102 "HDR_M254_RING-2X16" HDR_M254_RING-2X16 50,55.332 r0 top
J204 "U.FL" HRS_U.FL-R-SMT 87.3,41.7 r180 bottom
L1 "742792662" COIL_WURTH_CBF_0603 72.85,7.935 r90 top
L600 "742792662" COIL_WURTH_CBF_0603 10.235,53.926 r0 top
L700 "742792796" COIL_0402 24.125,37.5 r0 top
L702 "74279266" COIL_WURTH_CBF_0603 43.1,34.05 r180 top
L704 "742792796" COIL_0402 24,51.6 r0 top
L800 "742792796" COIL_0402 74.574,33.978 r180 top
L801 "742792796" COIL_0402 54.175,37.3 r180 top
L900 "74279266" COIL_WURTH_CBF_0603 38.39,50.035 r0 top
LABEL2 "Comment" LABEL_4CORNERS_19.0X6.0 10.25,12.425 r180 bottom
LED2 "RGB" LED_LUMEX_SML-LX0404-4 68.5,13 r0 top
LED900 "YELLOW" LED_0402_CAT2 87.25,56 r90 top
LED901 "BLUE" LED_0402_CAT2 14.625,49.85 r0 top
LED903 "RED" LED_0402 20.5,47.6 r180 top
LED904 "LED_G_R" LED_AVAGO_HSMF-C165-4 20.5,49.4 r0 top
LOGO3 "Comment" LOGO_SILABS_W14.0_SILK 79.375,16 r0 top
LOGO5 "Comment" LOGO_SILABS_W18.0 95,15.6 r180 bottom
LOGO_BEE "Comment" LOGO_BEE_H7.0 98,41.6 r0 top
LOGO_SEGGER "Comment" LOGO_SEGGER_10.0X5.0_SM 6.2,39 r0 top
M1 "HOLE_PTH_3MM" HOLE_3.0_5.0_PL 112,57 r0 top
M2 "Comment" HOLE_3.0_NPL 112,3 r0 top locked
M3 "Comment" HOLE_3.0_NPL 15.5,39 r90 top
M4 "Comment" ADHESIVE_PAD_25.0X4.0 60,22.65 r90 top
M5 "Comment" ADHESIVE_PAD_25.0X4.0 38.95,22.65 r90 top
OLED1 "Comment" OLED_LS013B7DH03 46.425,38.75 r0 top
P100 "L-KLS1-242D-1.2-10" KLS_KLS1-242D_FPC_0.5-10 45.25,30.175 r0 top
P101 "HEADER_2X10_2.54MM_TH" WCON_1125B-1210_HOR_PEG-2X10 113,19.84 r90 top locked
P101_TABLE "Comment" LABEL_P101_PIN_TABLE_SL 104.8,30 r180 bottom
P103 "USB_MICRO_AB" KLS_KLS1-5245 77.7,0 r0 top
P601 "FCI_10137065_USB-C_RCPT" FCI_10137065_USB-C_RCPT 4.85,52.5 r270 top
P700 "CR2032" BAT_HOLD_MPD_BK-912_CR2032 7,17 r270 top
P800 "HEADER_DEBUG_ETM" WCON_3132_HDR_M127_SMD-2X10 78.5,56 r180 top
P801 "HEADER_2X10_1.27MM_SMD" HDR_SULLINS_M127_PEG-2X10 101.08,56 r180 top
Q100 "DMN5L06VK" SOT563 40.275,24.89 r270 top
Q600 "BSS84" SOT563 20.95,25.225 r90 top
Q601 "DMN5L06VK" SOT563 22.9,25.225 r90 top
Q602 "BSS84" SOT563 30.2,25.225 r0 top
Q703 "DMG3415" X2-DFN2015-3_DIODES 14.225,4.55 r90 top
Q800 "DMN5L06VK" SOT563 67.825,37.3 r270 top
Q807 "DMN5L06VK" SOT563 63.775,29.5 r180 top
R5 "0R" R0402 86.925,41.2 r270 top
R7 "100R" R0402 110.6,12.675 r270 top
R9 "1K" R0201 103.5,14.8 r270 top
R100 "1M" R0201 51,12 r90 top
R101 "1M" R0201 38.429,12.033 r90 top
R104 "100R" R0402 50.847,13.67 r270 top
R105 "100R" R0402 38.85,13.675 r270 top
R111 "10K" R0201 83,12.9 r225 top
R113 "100R" R0402 90.66,5.355 r45 top
R118 "0R" R0402 74.4,11.2 r90 top
R119 "0R" R0402 75.8,11.2 r90 top
R120 "24K" R0402 79,26.5 r270 top
R121 "47K" R0402 80.3,26.5 r90 top
R124 "15K" R0201 82.4,11.5 r45 top
R125 "10K" R0201 89.4,4.2 r45 top
R126 "33K" R0201 91.8,6.6 r45 top
R127 "60K4" R0201 84.4,13.5 r45 top
R130 "1R" R0402 40.454,50.219 r0 top
R135 "698R" R0402 69.8,13.1 r90 top
R136 "910R" R0402 68.944,14.734 r90 top
R137 "2K32" R0402 68.052,14.737 r90 top
R140 "100K" R0201 39.888,32.575 r90 top
R141 "10M" R0201 39.942,26.832 r0 top
R142 "100K" R0201 40.756,22.983 r270 top
R145 "0R" R0402 54.007,29.332 r90 top
R146 "0R" R0402 54.9,29.332 r270 top
R220 "49R9" R0402 87.5,38.7 r180 bottom
R300 "0R" R0402 78.525,35 r180 top
R301 "0R" R0402 83,39.8 r180 top
R302 "1K" R0402 64.625,33.825 r0 top
R600 "10K" R0201 20.782,55.497 r0 top
R601 "180K" R0201 20.382,53.897 r270 top
R602 "110K" R0201 20.982,53.897 r90 top
R620 "5K1" R0201 11.924,52.88 r180 top
R621 "5K1" R0201 10.95,51.1 r180 top
R622 "47R" R0402 21.4,28.125 r0 top
R623 "10K" R0201 21.2,27.225 r180 top
R628 "1M" R0402 22.9,26.875 r180 top
R629 "1K" R0201 64.719,26.163 r180 top
R630 "4K7" R0201 52.15,32.5 r270 top
R631 "10K" R0201 51.6,32.5 r90 top
R633 "47K" R0201 50.5,32.5 r270 top
R634 "47K" R0201 49.95,32.5 r90 top
R636 "47K" R0201 47.2,32.5 r90 top
R637 "47K" R0201 46.65,32.5 r90 top
R639 "47K" R0201 48.85,32.5 r90 top
R640 "47K" R0201 48.3,32.5 r90 top
R672 "1K" R0201 24.15,26.525 r90 top
R674 "4K7" R0201 26.56,27.49 r0 top
R675 "3R3" R0402 32.332,26.05 r0 top
R679 "0R" R0402 29.085,26.761 r180 top
R681 "33R" R0402 28.38,23.172 r270 top
R686 "0R" R0402 68.008,23.984 r0 top
R687 "3R3" R0402 29.629,23.333 r270 top
R688 "4K7" R0201 67.786,27.233 r180 top
R690 "33R" R0402 64.471,24.944 r180 top
R691 "1M" R0402 63.027,26.187 r180 top
R700 "10K" R0201 32.627,28.911 r270 top
R701 "4R7" R1206 29.75,34.7 r180 top
R702 "180K" R0603 30.516,29.021 r180 top
R703 "110K" R0603 30.105,30.856 r270 top
R705 "267R" R0402 39.993,36.929 r270 top
R706 "10K2" R0402 40.87,37.444 r90 top
R707 "24K9" R0402 44.523,37.189 r270 top
R708 "1M" R0201 44.4,35.475 r90 top
R709 "1K8" R0603 30.35,36.9 r270 top
R710 "1K8" R0603 29.15,36.9 r270 top
R717 "10R" R0402 26.05,37.5 r0 top
R718 "12K" R0603 31.925,40.225 r90 top
R731 "1R" R0402 23.95,50.675 r0 top
R760 "330K" R0201 25.573,33.403 r90 top
R763 "100K" R0201 22.979,34.098 r0 top
R764 "90R9" R0603 26.8,48.325 r90 top
R765 "51K" R0603 26.8,45.825 r270 top
R767 "160R" R0603 26.775,43.35 r90 top
R768 "90R9" R0603 32,48.45 r90 top
R769 "51K" R0603 32,45.9 r270 top
R771 "51K" R0603 32,43.375 r90 top
R792 "1K" R0201 13.4,2.9 r0 top
R793 "0R" R0402 20.025,11.053 r90 top
R801 "47K" R0201 67.849,43.093 r270 top
R805 "33R" R0402 66.85,41.95 r0 top
R807 "100K" R0201 69.325,47.375 r90 top
R808 "100K" R0201 70.475,26.85 r90 top
R809 "100K" R0201 54.925,38.425 r270 top
R810 "33R" R0402 53.7,38.725 r0 top
R814 "100K" R0201 71.232,25.13 r180 top
R815 "1K" R0201 66.59,36.842 r270 top
R816 "100K" R0402 72.4,45.7 r180 top
R817 "100K" R0201 71.85,47.15 r180 top
R838 "100K" R0201 61.901,28.996 r180 top
R839 "10M" R0201 64.1,28.225 r180 top
R840 "100K" R0201 65.4,30.75 r90 top
R841 "1K" R0201 64.104,27.652 r0 top
R850 "100K" R0201 50.9,47.642 r90 top
R851 "100K" R0201 67.9,40.912 r180 top
R852 "100K" R0201 62.5,39.25 r180 top
R853 "100K" R0201 68.075,34.825 r180 top
R882 "220R" R0402 54.85,47.95 r270 top
R900 "2K05" R0201 87.235,54.44 r90 top
R902 "33R" R0402 41.65,41.75 r0 top
R903 "5K76" R0201 14.625,49.05 r180 top
R904 "33R" R0402 41.65,40.875 r0 top
R906 "10K" R0201 54.45,35 r90 top
R907 "4K7" R0201 54.965,49.726 r180 top
R908 "4K7" R0201 54.898,49.168 r180 top
R909 "10K" R0201 54.976,50.251 r180 top
R912 "2K15" R0201 20.5,46.8 r180 top
R919 "1K" R0201 18.6,49.05 r0 top
R920 "2K37" R0201 18.6,49.75 r0 top
R930 "1K" R0201 47.902,49.863 r0 top
R931 "1K" R0201 47.9,50.4 r0 top
R950 "100K" R0201 54.9,44.2 r270 top
R981 "100K" R0201 55.05,43.225 r0 top
R982 "10K" R0201 45.954,37.531 r270 top
RP800 "33R" RES_MNR04-8 54.55,40.4 r90 top
RP801 "33R" RES_MNR04-8 66.7,43.55 r90 top
ST701 "2X1 2.54MM" HDR_M254-1X2 2.875,2.08 r90 top
SW1 "PTS810" SW_CK_PTS810_SJM_250 107.2,13 r0 top
SW100 "PTS810" SW_CK_PTS810_SJM_250 54,13 r0 top locked
SW101 "PTS810" SW_CK_PTS810_SJM_250 42,13 r0 top locked
SW105 "ALPS_SKRH_4" SW_ALPS_SKRHAAE010 87.05,9 r135 top
SW704 "SW_DP3T_0" CK_DP3T_JS203011SCQN 22.025,5.05 r0 top locked
TAB1 "Comment" TAB_V-CUT_L7.0_W2.4 12,0 r180 top
TAB2 "Comment" TAB_V-CUT_L7.0_W2.4 60,0 r180 top
TAB3 "Comment" TAB_V-CUT_L7.0_W2.4 98,0 r180 top
TAB4 "Comment" TAB_V-CUT_L7.0_W2.4 12,60 r0 top
TAB5 "Comment" TAB_V-CUT_L7.0_W2.4 60,60 r0 top
TAB6 "Comment" TAB_V-CUT_L7.0_W2.4 98,60 r0 top
TP150 "TP_SMD" TP_1.0_SMD 38.3,32.3 r270 bottom
TP151 "TP_SMD" TP_1.0_SMD 38.3,27.8 r0 bottom
TP152 "TP_SMD" TP_1.0_SMD 40.8,28.4 r270 bottom
TP153 "TP_SMD" TP_1.0_SMD 47.8,27.6 r270 bottom
TP154 "TP_SMD" TP_1.0_SMD 101.9,14.5 r270 bottom
TP156 "TP_SMD" TP_1.0_SMD 15.3,4.6 r180 bottom
TP157 "TP_SMD" TP_1.0_SMD 78.5,31.2 r270 bottom
TP700 "TP_SMD" TP_1.0_SMD 29.9,34.4 r90 bottom
TP701 "TP_SMD" TP_1.0_SMD 28.6,36 r90 bottom
TP703 "TP_SMD" TP_1.0_SMD 28.9,4.7 r180 bottom
TP704 "TP_SMD" TP_1.0_SMD 20,5.2 r90 bottom
TP705 "TP_SMD" TP_1.0_SMD 41.6,36.2 r180 bottom
TP706 "TP_SMD" TP_1.0_SMD 26.9,49.425 r90 bottom
TP707 "TP_SMD" TP_1.0_SMD 32.05,49.575 r90 bottom
TP708 "TP_SMD" TP_1.0_SMD 48.8,34.8 r90 bottom
TP709 "TP_SMD" TP_1.0_SMD 23.425,2.725 r90 bottom
TP711 "TP_SMD" TP_1.0_SMD 39.7,34.7 r90 bottom
TP712 "TP_SMD" TP_1.0_SMD 39.7,38.8 r90 bottom
TP713 "TP_SMD" TP_1.0_SMD 43.8,36.7 r90 bottom
TP714 "TP_SMD" TP_1.0_SMD 43.2,34.1 r90 bottom
TP715 "TP_SMD" TP_1.0_SMD 23.3,35.4 r180 bottom
TP923 "TP_SMD" TP_1.0_SMD 46.5,34.2 r90 bottom
TP930 "TP_SMD" TP_1.0_SMD 56.5,32.5 r180 bottom
TPJ403 "TP_SMD" TP_1.0_SMD 72.95,10.45 r90 bottom
TPJ404 "TP_SMD" TP_1.0_SMD 77.247,10.45 r90 bottom
TPJ405 "TP_SMD" TP_1.0_SMD 74.098,6.252 r90 bottom
TPJ600 "TP_SMD" TP_1.0_SMD 14.353,32.302 r90 bottom
TPJ606 "TP_SMD" TP_1.0_SMD 97.404,47.202 r90 bottom
TPJ607 "TP_SMD" TP_1.0_SMD 66.653,44.101 r90 bottom
TPJ608 "TP_SMD" TP_1.0_SMD 34.528,20.527 r90 bottom
TPJ611 "TP_SMD" TP_1.0_SMD 10.15,51.3 r180 bottom
TPJ612 "TP_SMD" TP_1.0_SMD 10.15,53.85 r180 bottom
TPJ613 "TP_SMD" TP_1.0_SMD 12.7,53.85 r180 bottom
TPJ614 "TP_SMD" TP_1.0_SMD 7.55,49.8 r180 bottom
TPJ650 "TP_SMD" TP_1.0_SMD 108.25,43.248 r90 bottom
TPJ651 "TP_SMD" TP_1.0_SMD 108.25,39.7 r90 bottom
TPJ652 "TP_SMD" TP_1.0_SMD 61.303,16.102 r90 bottom
TPJ653 "TP_SMD" TP_1.0_SMD 51.953,16.102 r90 bottom
TPJ811 "TP_SMD" TP_1.0_SMD 77.9,52.7 r180 bottom
TPJ812 "TP_SMD" TP_1.0_SMD 81.65,53.45 r180 bottom
TPJ814 "TP_SMD" TP_1.0_SMD 84.35,54.3 r180 bottom
TPJ817 "TP_SMD" TP_1.0_SMD 102.65,48.35 r180 bottom
TPJ818 "TP_SMD" TP_1.0_SMD 71.55,40.95 r180 bottom
TPJ820 "TP_SMD" TP_1.0_SMD 80.2,50.95 r180 bottom
TPJ900 "TP_SMD" TP_1.0_SMD 41.602,37.9 r90 bottom
TPJ901 "TP_SMD" TP_1.0_SMD 44.053,38.55 r90 bottom
TPJ902 "TP_SMD" TP_1.0_SMD 24.6,41.4 r180 bottom
TPJ908 "TP_SMD" TP_1.0_SMD 43.952,45.601 r90 bottom
TPJ909 "TP_SMD" TP_1.0_SMD 42.651,43.427 r90 bottom
TPJ910 "TP_SMD" TP_1.0_SMD 48.003,29.65 r90 bottom
TPJ911 "TP_SMD" TP_1.0_SMD 45.453,28.85 r90 bottom
TPJ912 "TP_SMD" TP_1.0_SMD 50.751,34.225 r90 bottom
TPJ913 "TP_SMD" TP_1.0_SMD 50.751,30.501 r90 bottom
TPJ950 "TP_SMD" TP_1.0_SMD 24.452,17.1 r90 bottom
TPJ953 "TP_SMD" TP_1.0_SMD 42.001,25.251 r90 bottom
TPJ954 "TP_SMD" TP_1.0_SMD 43.253,27.501 r90 bottom
TPJ955 "TP_SMD" TP_1.0_SMD 44.503,25.251 r90 bottom
TPJ956 "TP_SMD" TP_1.0_SMD 52.753,39.251 r90 bottom
TPJ957 "TP_SMD" TP_1.0_SMD 51.799,27.599 r180 bottom
TPJ958 "TP_SMD" TP_1.0_SMD 53.15,25.45 r180 bottom
TPJ959 "TP_SMD" TP_1.0_SMD 54.499,27.599 r90 bottom
TPJ960 "TP_SMD" TP_1.0_SMD 53.899,32.598 r90 bottom
TPJ961 "TP_SMD" TP_1.0_SMD 53.95,30.05 r180 bottom
U1 "EFM8UB20F64G-B-QFP48" QFP48_SI_EFM8 86.175,32.9 r0 top locked
U100 "TS3A44159" UQFN16_M040_1.8X2.6_TI_RSV 40.39,30.175 r0 top
U600 "LP3982ILD-ADJ" WSON8_M050_3.0X2.5_EP_TI_NGM 18.432,55.147 r0 top
U603 "TLV70536" DSBGA4_M040_0.8X0.8_TI_YFP 44.35,32.45 r180 top
U606 "MCP6001T" SC70-5 26.9,25.675 r270 top
U622 "MCP6001T" SC70-5 67.5,25.7 r180 top
U700 "SIP32431" TDFN4_M050_1.6X1.2_EP_VISH 24.5,33.35 r90 top
U701 "LP3982ILD-ADJ" WSON8_M050_3.0X2.5_EP_TI_NGM 32.125,31.275 r270 top
U702 "TS3A4751" QFN14_M040_2.0X2.0_TI_RUC 42.7,36.675 r180 top
U703 "LTC6102IDD" DFN8_M050_3.0X3.0_EP_LT_DD 28.85,39.9 r180 top
U704 "AD8655" MSOP8_M065_W3.0 23.95,45.425 r90 top
U705 "AD8655" MSOP8_M065_W3.0 29.125,45.425 r90 top
U800 "74LVC4066" DHVQFN14_M050_2.5X3_EP_NXP 70.9,43.6 r270 top
U802 "74LVC4066" DHVQFN14_M050_2.5X3_EP_NXP 70.9,39.1 r270 top
U803 "74LVC1T45" X2-DFN1010-6_M035_DIODES 70.375,47.425 r0 top
U804 "74LVC2G125" DSBGA8_M050_0.9X1.9_TI_YZP 51.575,38.15 r180 top
U805 "TS3A4751" QFN14_M040_2.0X2.0_TI_RUC 64.775,37.07 r90 top
U806 "74LVC4066" DHVQFN14_M050_2.5X3_EP_NXP 70.9,34.6 r270 top
U807 "74LVC1T45" X2-DFN1010-6_M035_DIODES 71.413,26.175 r270 top
U808 "74LVC8T245" VQFN24_M050_3.5X5.5_EP_TI_RHL 63.4,43.05 r0 top
U809 "74LVC2G125" DSBGA8_M050_0.9X1.9_TI_YZP 52.3,41.675 r180 top
U810 "74LVC4066" DHVQFN14_M050_2.5X3_EP_NXP 70.9,30.1 r270 top
U812 "TS3A4751" QFN14_M040_2.0X2.0_TI_RUC 67.1,30.05 r90 top
U860 "74LVC1T45" X2-DFN1010-6_M035_DIODES 51.95,48 r180 top
U861 "74LVC1T45" X2-DFN1010-6_M035_DIODES 67.6,39.9 r90 top
U862 "74LVC1T45" X2-DFN1010-6_M035_DIODES 62.45,38.2 r90 top
U863 "74LVC1T45" X2-DFN1010-6_M035_DIODES 67.7,33.8 r90 top
U900 "EFM32GG12B410F1024GL120-A" BGA120_M050_7.0X7.0_EFM32GGR 46.6,44.5 r180 top
U901 "M24C02" TDFN8_M050_2.0X3.0_EP 51.895,49.95 r0 top
U902 "MX25R8035F" BGA8_M040_1.24X1.75_WLCSP 53.4,34.3 r0 top
U910 "ADC084S021" VSSOP10_M050_W3.0_TI_DGS 48.425,35.025 r0 top
U950 "TS3A4751" QFN14_M040_2.0X2.0_TI_RUC 53.225,44.9 r270 top
X900 "48 MHz" X_KDS_DSX211SH_2.0X1.65-4 45.7,49.75 r0 top

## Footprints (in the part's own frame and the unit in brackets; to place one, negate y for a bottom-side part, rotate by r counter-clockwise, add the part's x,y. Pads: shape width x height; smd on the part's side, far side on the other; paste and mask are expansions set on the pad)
ADHESIVE_PAD_25.0X4.0 [mm] "Adhesive for Sharp Display"
  Top Layer keep-out region: 0,4 0,0.001 25,0.001 25,4.001 0,4
  silkscreen extent 0,0 25,4, body extent 0,0 25,4, height 0.2
BAT_HOLD_MPD_BK-912_CR2032 [mil] "MPD Battery Holder BK-912 (for CR2032)"
  rrect20% 110x200 smd: 1(-430,0) 1(430,0)
  round 157.48 smd paste-295.67 mask-82.68: 2(0,0)
  body extent -450,-394 450,393, height 171
BGA8_M040_1.24X1.75_WLCSP [mm] "BGA, 8 pin. U100"
  round 0.21 smd mask+0.05: A1(-0.35,0.4) A3(0.35,0.4) B2(0,0.2) C1(-0.35,0) C3(0.35,0) D2(0,-0.2) E1(-0.35,-0.4) E3(0.35,-0.4)
  body extent -0.63,-0.89 0.63,0.88, height 0.52
BGA120_M050_7.0X7.0_EFM32GGR [mm] "BGA, 120 Leads, Body 7.0x7.0mmx1,30mm, Pitch 0.50mm (191111)"
  round 0.2 smd mask+0.04: A1(-3,3) A2(-2.5,3) A3(-2,3) A4(-1.5,3) A5(-1,3) A6(-0.5,3) A7(0,3) A8(0.5,3) A9(1,3) A10(1.5,3) A11(2,3) A12(2.5,3) A13(3,3) B1(-3,2.5) B2(-2.5,2.5) B3(-2,2.5) B4(-1.5,2.5) B5(-1,2.5) B6(-0.5,2.5) B7(0,2.5) B8(0.5,2.5) B9(1,2.5) B10(1.5,2.5) B11(2,2.5) B12(2.5,2.5) B13(3,2.5) C1(-3,2) C2(-2.5,2) C3(-2,2) C4(-1.5,2) C5(-1,2) C6(-0.5,2) C7(0,2) C8(0.5,2) C9(1,2) C10(1.5,2) C11(2,2) C12(2.5,2) C13(3,2) D1(-3,1.5) D2(-2.5,1.5) D3(-2,1.5) D11(2,1.5) D12(2.5,1.5) D13(3,1.5) E1(-3,1) E2(-2.5,1) E3(-2,1) E11(2,1) E12(2.5,1) E13(3,1) F1(-3,0.5) F2(-2.5,0.5) F3(-2,0.5) F11(2,0.5) F12(2.5,0.5) F13(3,0.5) G1(-3,0) G2(-2.5,0) G3(-2,0) G11(2,0) G12(2.5,0) G13(3,0) H1(-3,-0.5) H2(-2.5,-0.5) H3(-2,-0.5) H11(2,-0.5) H12(2.5,-0.5) H13(3,-0.5) J1(-3,-1) J2(-2.5,-1) J3(-2,-1) J11(2,-1) J12(2.5,-1) J13(3,-1) K1(-3,-1.5) K2(-2.5,-1.5) K3(-2,-1.5) K11(2,-1.5) K12(2.5,-1.5) K13(3,-1.5) L1(-3,-2) L2(-2.5,-2) L3(-2,-2) L4(-1.5,-2) L5(-1,-2) L6(-0.5,-2) L7(0,-2) L8(0.5,-2) L9(1,-2) L10(1.5,-2) L11(2,-2) L12(2.5,-2) L13(3,-2) M1(-3,-2.5) M2(-2.5,-2.5) M3(-2,-2.5) M4(-1.5,-2.5) M5(-1,-2.5) M6(-0.5,-2.5) M7(0,-2.5) M8(0.5,-2.5) M9(1,-2.5) M10(1.5,-2.5) M11(2,-2.5) M12(2.5,-2.5) M13(3,-2.5) N1(-3,-3) N2(-2.5,-3) N3(-2,-3) N4(-1.5,-3) N5(-1,-3) N6(-0.5,-3) N7(0,-3) N8(0.5,-3) N9(1,-3) N10(1.5,-3) N11(2,-3) N12(2.5,-3) N13(3,-3)
  body extent -3.5,-3.5 3.5,3.5, height 1.3
C0201 [mm] "Capacitor, 9291, HiDens (170502)"
  rrect25% 0.36x0.32 smd paste-0.015 mask+0.05: 1(-0.275,0) 2(0.275,0)
  Top Layer pour cut-out: -0.075,-0.2 -0.075,0.2 0.075,0.2 0.075,-0.2
  body extent -0.32,-0.13 0.32,0.13, height 0.3
C0402 [mm] "Chip Capacitor, 2-Leads, Body 1.0x0.5mm, IPC High Density (190308)"
  rrect20% 0.5x0.5 smd mask+0.051: 1(-0.5,0) 2(0.5,0)
  Top Layer pour cut-out: -0.225,-0.3 -0.225,0.3 0.225,0.3 0.225,-0.3
  body extent -0.5,-0.25 0.5,0.25, height 0.6
C0603 [mm] "Capacitor, 0603, HiDens (190130)"
  rrect25% 0.8x0.85 smd: 1(-0.7,0) 2(0.7,0)
  Top Layer pour cut-out: -0.275,-0.55 -0.275,0.55 0.275,0.55 0.275,-0.55
  body extent -0.88,-0.48 0.87,0.48, height 0.95
C0805 [mm] "Capacitor, 0805 HiDens (190717)"
  rrect25% 0.95x1.35 smd: 1(-0.8,0) 2(0.8,0)
  body extent -1.1,-0.64 1.1,0.64, height 1.45
CK_DP3T_JS203011SCQN [mm] "Switch, C & K DP3T JS203011SCQN (190314)"
  rrect50% 1.2x2.5 smd: 1(-4,-2.75) 2(-2,-2.75) 3(2,-2.75) 4(4,-2.75) 5(-4,2.75) 6(-2,2.75) 7(2,2.75) 8(4,2.75)
  body extent -6.5,-3.75 6.5,3.75, height 5.22
COIL_0402 [mm] "COIL_0402_L (3D from Wurth) (190308)"
  rrect20% 0.55x0.5 smd mask+0.051: 1(-0.525,0) 2(0.525,0)
  Top Layer pour cut-out: -0.225,-0.3 -0.225,0.3 0.225,0.3 0.225,-0.3
  body extent -0.5,-0.25 0.5,0.25, height 0.5
COIL_WURTH_CBF_0603 [mm] "COIL_WURTH_CBF_0603 (= L0603_0.8_L) (181031)"
  rrect10% 0.67x0.88 smd: 1(-0.665,0) 2(0.665,0)
  body extent -0.87,-0.48 0.87,0.48, height 0.95
DFN8_M050_3.0X3.0_EP_LT_DD [mm] "DFN 8 Lead, Pitch 0.5, 3.0x3.0x0.75 Exposed Pad, Linear Tech (171004)"
  rrect50% 0.7x0.25 smd paste-0.025 mask+0.07: 1(-1.4,0.75) 2(-1.4,0.25) 3(-1.4,-0.25) 4(-1.4,-0.75) 5(1.4,-0.75) 6(1.4,-0.25) 7(1.4,0.25) 8(1.4,0.75)
  rect 1x1.8 smd paste-1 mask+0: 9(0,0)
  Top Layer region: 0.825,1.2 -0.693,1.2 -0.825,1.095 -0.825,-1.2 0.825,-1.2
  body extent -1.56,-1.55 1.56,1.55, height 0.8
DFN2111-7_M050_1.2X2.1_NXP [mm] "DFN2111-7 NXP Pitch 035 1.2x2.1x0.5, NXP (190312)"
  rrect20% 0.53x0.19 smd mask+0.05: 1(-0.415,0.75) 2(-0.415,0.25) 3(-0.415,-0.25) 4(-0.415,-0.75) 5(0.415,-0.5) 6(0.415,0) 7(0.415,0.5)
  body extent -0.6,-1.05 0.6,1.05, height 0.51
DHVQFN14_M050_2.5X3_EP_NXP [mm] "DHVQFN, 14 Leads, 2.5x3.0x0.85, Pitch 0.50, Thermal Pad 1.0x1.5 (190314)"
  oval 0.3x0.7 smd: 1(-0.25,1.45) 7(-0.25,-1.45) 8(0.25,-1.45) 14(0.25,1.45)
  oval 0.7x0.3 smd: 2(-1.2,1) 3(-1.2,0.5) 4(-1.2,0) 5(-1.2,-0.5) 6(-1.2,-1) 9(1.2,-1) 10(1.2,-0.5) 11(1.2,0) 12(1.2,0.5) 13(1.2,1)
  rrect10% 1x1.5 smd: 17(0,0)
  body extent -1.25,-1.5 1.25,1.5, height 1.1
DSBGA4_M040_0.8X0.8_TI_YFP [mm] "DS-BGA, 4 Leads, Body 0.8x0.8 H:0.5, Pitch 0.40"
  round 0.23 smd mask+0.04: A1(-0.2,0.2) A2(0.2,0.2) B1(-0.2,-0.2) B2(0.2,-0.2)
  body extent -0.4,-0.4 0.4,0.4, height 0.51
DSBGA8_M050_0.9X1.9_TI_YZP [mm] "DS-BGA, 8 Leads, Body 0.9x1.9 H:0.5, Pitch 0.50"
  round 0.23 smd: A1(-0.25,0.75) A2(0.25,0.75) B1(-0.25,0.25) B2(0.25,0.25) C1(-0.25,-0.25) C2(0.25,-0.25) D1(-0.25,-0.75) D2(0.25,-0.75)
  body extent -0.45,-0.95 0.45,0.95, height 0.51
FCI_10137065_USB-C_RCPT [mm] "FCI AMPHENOL 10137065 USB-C Receptacle (Slot PinInPaste) (180404)"
  oval 1.3x2.6 hole 0.7 slot 2 at 90 deg: 25(-4.32,-3.05) 26(4.32,-3.05)
  oval 1.3x2.6 on Top Paste: 25(-4.32,-3.05) 26(4.32,-3.05)
  oval 1.2x2.489 on Top Paste: 27(-4.32,2)
  oval 1.2x2.5 hole 0.6 slot 1.9 at 90 deg paste+0: 27(-4.32,2)
  oval 1.638x1.194 on Top Paste: 27(-4.025,1.35)
  oval 1.647x1.2 hole 0.6 slot 1.247 at 0 deg: 27(-4.025,1.35)
  oval 1.847x1.2 hole 0.6 slot 1.247 at 0 deg: 28(4.025,1.35)
  oval 1.841x1.194 on Top Paste: 28(4.025,1.35)
  oval 1.2x2.5 hole 0.6 slot 1.9 at 90 deg: 28(4.32,2)
  oval 1.194x2.489 on Top Paste: 28(4.32,2)
  rrect20% 0.27x0.9 smd mask+0.076: A1(-2.625,2.7) A2(-2.125,2.7) A3(-1.625,2.7) A4(-1.125,2.7) A5(-0.625,2.7) A6(-0.125,2.7) A7(0.375,2.7) A8(0.875,2.7) A9(1.375,2.7) A10(1.875,2.7) A11(2.375,2.7) A12(2.875,2.7)
  rrect20% 0.27x0.8 smd mask+0.076: B1(2.625,1.1) B2(2.125,1.1) B3(1.625,1.1) B4(1.125,1.1) B5(0.625,1.1) B6(0.125,1.1) B7(-0.375,1.1) B8(-0.875,1.1) B9(-1.375,1.1) B10(-1.875,1.1) B11(-2.375,1.1) B12(-2.875,1.1)
  round 0 hole 0.6 unplated mask+0.102: M1(-3.6,0)
  round 0 hole 0.5 slot 0.85 at 0 deg unplated mask+0.102: M2(3.6,0)
  Top Layer keep-out region: -3.9,-4.85 3.9,-4.85 3.9,0.4 -3.9,0.4
  body extent -4.47,-5.3 4.47,2.85, height 3.14
HDR_M254-1X2 [mm] "Connector; Header; 2 Position (170508)"
  round 1.6 hole 1: 1(0,0) 2(2.54,0)
  body extent -1.07,-1.17 3.61,1.17, height 8.12
HDR_M254_RING-2X16 [mm] "Connector; Header; 2x16 Position, 2.54mm (190312)"
  round 1.6 hole 1: 1(-19.05,-1.27) 2(-19.05,1.27) 3(-16.51,-1.27) 4(-16.51,1.27) 5(-13.97,-1.27) 6(-13.97,1.27) 7(-11.43,-1.27) 8(-11.43,1.27) 9(-8.89,-1.27) 10(-8.89,1.27) 11(-6.35,-1.27) 12(-6.35,1.27) 13(-3.81,-1.27) 14(-3.81,1.27) 15(-1.27,-1.27) 16(-1.27,1.27) 17(1.27,-1.27) 18(1.27,1.27) 19(3.81,-1.27) 20(3.81,1.27) 21(6.35,-1.27) 22(6.35,1.27) 23(8.89,-1.27) 24(8.89,1.27) 25(11.43,-1.27) 26(11.43,1.27) 27(13.97,-1.27) 28(13.97,1.27) 29(16.51,-1.27) 30(16.51,1.27) 31(19.05,-1.27) 32(19.05,1.27)
HDR_SULLINS_M127_PEG-2X10 [mil] "Sullins, GRPB102VQS (180319)"
  rrect50% 30x87 smd: 1(-25,-72.5) 2(-25,72.5) 3(25,-72.5) 4(25,72.5) 5(75,-72.5) 6(75,72.5) 7(125,-72.5) 8(125,72.5) 9(175,-72.5) 10(175,72.5) 11(225,-72.5) 12(225,72.5) 13(275,-72.5) 14(275,72.5) 15(325,-72.5) 16(325,72.5) 17(375,-72.5) 18(375,72.5) 19(425,-72.5) 20(425,72.5)
  round 0 hole 39.37 unplated mask+3.94: M1(0,0) M2(400,0)
  body extent -50,-100 450,101, height 197
HOLE_3.0_5.0_PL [mm] "Hole 3.0 mm, Plated (171122)"
  round 5 hole 3: 1(0,0)
HOLE_3.0_NPL [mm] "HOLE_3.0_NPL (170815)"
  round 0 hole 3 unplated mask+0.2: 1(0,0)
  body extent -1.5,-1.5 1.5,1.5
HRS_U.FL-R-SMT [mm] "COAX_HIROSE_U.FL_CL331-0471 (170228)"
  rrect20% 1.05x1.1 smd mask+0.051: 1(0,-1.6)
  rrect20% 1.05x2.25 smd mask+0.051: 2(1.5,0) 3(-1.5,0)
  Top Layer pour cut-out: 0.85,-0.9 -0.85,-0.9 -0.85,-0.9 -0.85,1.2 0.85,1.2 0.85,1.2
  body extent -1.3,-1.3 1.3,1.55, height 0.9
KLS_KLS1-242D_FPC_0.5-10 [mm] "KLS1-242D-1.2-10 (3D IS FROM MOL 5450) (201021)"
  rrect50% 0.3x1.25 smd mask+0.076: 1(0,0) 2(0.5,0) 3(1,0) 4(1.5,0) 5(2,0) 6(2.5,0) 7(3,0) 8(3.5,0) 9(4,0) 10(4.5,0)
  rrect5% 2x2.45 smd: 11(-1.69,-2.6) 12(6.19,-2.6)
  body extent -2.85,-5.05 7.35,-0.05, height 1.2
KLS_KLS1-5245 [mm] "Micro USB 5P Femalw type AB"
  rrect20% 0.35x1.7 smd mask+0.076: 1(-1.3,4.85) 2(-0.65,4.85) 3(0,4.85) 4(0.65,4.85) 5(1.3,4.85)
  rrect50% 1.3x1.55 hole 0.55 slot 0.75 at 0 deg: 6(-2.225,5.05) 7(2.225,5.05)
  rrect50% 1.45x2.1 hole 0.5 slot 1.1 at 90 deg paste+0: 8(-4.175,2.15) 9(4.175,2.15)
  body extent -4.02,-0.53 4.03,5.27, height 3.1
LABEL_4CORNERS_19.0X6.0 [mm]
  silkscreen extent -9.5,-3 9.5,3
LABEL_P101_PIN_TABLE_SL [mm]
  silkscreen extent -2.4,-12.5 2.4,12.5
LED_0402 [mm] "Chip Diode, 2-Leads, Body 1.00x0.50mm, IPC High Density (170127)"
  rrect10% 0.45x0.6 smd: 1(-0.45,0) 2(0.45,0)
  body extent -0.55,-0.33 0.55,0.33, height 0.25
LED_0402_CAT2 [mm] "(200921)"
  rrect10% 0.45x0.6 smd: 1(-0.45,0) 2(0.45,0)
  body extent -0.55,-0.33 0.55,0.33, height 0.25
LED_AVAGO_HSMF-C165-4 [mm] "LED (dual) Avago HSMF-C165 Grn+Red 1.6x0.8x0.5 (200226)"
  rrect20% 0.7x0.4 smd: 1(-0.65,-0.35) 2(-0.65,0.35) 3(0.65,0.35) 4(0.65,-0.35)
  body extent -0.8,-0.4 0.8,0.4, height 0.52
LED_LUMEX_SML-LX0404-4 [mm] "LED, LUMEX, SML LX0404 1.0x1.0x0.25 NB! Pin numbering (180111)"
  rrect25% 0.45x0.45 smd mask+0.05: 1(-0.425,-0.425) 2(-0.425,0.425) 3(0.425,0.425) 4(0.425,-0.425)
  body extent -0.5,-0.5 0.5,0.5, height 0.31
LOGO_BEE_H7.0 [mm] "Silicon Labs Logo Bee (210415)"
  silkscreen extent -3.58,0 3.61,6.92
LOGO_SEGGER_10.0X5.0_SM [mm] "Logo, Segger 10.0x5.0, Top Solder + M19 + Top Overlay"
LOGO_SILABS_W14.0_SILK [mm] "LOGO_SILABS_W14.0 SILKSCREEN ONLY"
  silkscreen extent 0.03,0 13.99,6.83
LOGO_SILABS_W18.0 [mm]
  silkscreen extent 0.02,0.02 16.98,8.32
MSOP8_M065_W3.0 [mm] "MSOP, 8-Leads, Body 3.0x3.0mm, Pitch 0.65mm (170921)"
  rrect20% 0.889x0.42 smd mask+0.048: 1(-2.105,0.975) 2(-2.105,0.325) 3(-2.105,-0.325) 4(-2.105,-0.975) 5(2.106,-0.975) 6(2.106,-0.325) 7(2.106,0.325) 8(2.106,0.975)
  body extent -1.55,-1.55 1.55,1.55, height 1.11
OLED_LS013B7DH03 [mm] "LS013B7DH03 (200526)"
  body extent -13.3,-18.6 13.3,13.23, height 3.8
QFN14_M040_2.0X2.0_TI_RUC [mm] "QFN 14 Leads, Pitch 0.4 mm, 2.0 x 2.0 H: 0.37, TI: RUC (180613)"
  rrect20% 0.68x0.2 smd: 1(-0.885,0.8) 2(-0.885,0.4) 3(-0.885,0) 4(-0.885,-0.4) 5(-0.885,-0.8) 8(0.885,-0.8) 9(0.885,-0.4) 10(0.885,0) 11(0.885,0.4) 12(0.885,0.8)
  rrect20% 0.2x0.68 smd: 6(-0.2,-0.885) 7(0.2,-0.885) 13(0.2,0.885) 14(-0.2,0.885)
  body extent -1,-1 1,1, height 0.41
QFP48_SI_EFM8 [mm]
  rect 1.5x0.3 smd mask+0.075: 1(-4.2,2.75) 2(-4.2,2.25) 3(-4.2,1.75) 4(-4.2,1.25) 5(-4.2,0.75) 6(-4.2,0.25) 7(-4.2,-0.25) 8(-4.2,-0.75) 9(-4.2,-1.25) 10(-4.2,-1.75) 11(-4.2,-2.25) 12(-4.2,-2.75) 25(4.2,-2.75) 26(4.2,-2.25) 27(4.2,-1.75) 28(4.2,-1.25) 29(4.2,-0.75) 30(4.2,-0.25) 31(4.2,0.25) 32(4.2,0.75) 33(4.2,1.25) 34(4.2,1.75) 35(4.2,2.25) 36(4.2,2.75)
  rect 0.3x1.5 smd mask+0.075: 13(-2.75,-4.2) 14(-2.25,-4.2) 15(-1.75,-4.2) 16(-1.25,-4.2) 17(-0.75,-4.2) 18(-0.25,-4.2) 19(0.25,-4.2) 20(0.75,-4.2) 21(1.25,-4.2) 22(1.75,-4.2) 23(2.25,-4.2) 24(2.75,-4.2) 37(2.75,4.2) 38(2.25,4.2) 39(1.75,4.2) 40(1.25,4.2) 41(0.75,4.2) 42(0.25,4.2) 43(-0.25,4.2) 44(-0.75,4.2) 45(-1.25,4.2) 46(-1.75,4.2) 47(-2.25,4.2) 48(-2.75,4.2)
  body extent -4.5,-4.5 4.5,4.5, height 1.5
R0201 [mm] "Resistor (Chip2PinSM127P600-8N) (170921)"
  rrect25% 0.34x0.32 smd: 1(-0.3,0) 2(0.3,0)
  Top Layer pour cut-out: -0.1,-0.2 -0.1,0.2 0.1,0.2 0.1,-0.2
  body extent -0.32,-0.13 0.32,0.13, height 0.3
R0402 [mm] "Chip Resistor, 2-Leads, Body 1.0x0.5mm, HiDens (190308)"
  rrect20% 0.6x0.6 smd mask+0.051: 1(-0.45,0) 2(0.45,0)
  Top Layer pour cut-out: -0.125,-0.3 -0.125,0.3 0.125,0.3 0.125,-0.3
  body extent -0.5,-0.25 0.5,0.25, height 0.6
R0603 [mm] "Chip Resistor, 0603, HiDens (190130)"
  rrect25% 0.85x0.9 smd: 1(-0.7,0) 2(0.7,0)
  Top Layer pour cut-out: -0.25,-0.575 -0.25,0.575 0.25,0.575 0.25,-0.575
  body extent -0.88,-0.48 0.87,0.48, height 0.95
R1206 [mm] "Resistor, 1206, HiDens (191114)"
  rrect25% 0.85x1.65 smd paste-0.04 mask+0.07: 1(-1.425,0) 2(1.425,0)
  body extent -1.6,-0.8 1.6,0.8, height 1
RES_MNR04-8 [mm] "Resistor Array, ROHM MNR04 8-Pin 2.0x1.0x0.35 (!80615)"
  rrect20% 0.4x0.5 smd: 1(-0.75,-0.45) 4(0.75,-0.45) 5(0.75,0.45) 8(-0.75,0.45)
  rrect20% 0.3x0.5 smd: 2(-0.25,-0.45) 3(0.25,-0.45) 6(0.25,0.45) 7(-0.25,0.45)
  body extent -1,-0.4 1,0.4, height 0.5
SC70-5 [mm] "SC70-5 = SOT353, HiDens (170511)"
  rrect25% 0.6x0.4 smd paste-0.03 mask+0.05: 1(-0.95,0.65) 2(-0.95,0) 3(-0.95,-0.65) 4(0.95,-0.65) 5(0.95,0.65)
  body extent -1.12,-0.97 1.16,1.03, height 0.95
SOT563 [mm] "SOT563 (_M050_W1.2_), 6-Leads, Body 1.60x1.20, Pitch 0.5, HiDens (170926)"
  rrect25% 0.6x0.3 smd: 1(-0.65,0.5) 2(-0.65,0) 3(-0.65,-0.5) 4(0.65,-0.5) 5(0.65,0) 6(0.65,0.5)
  body extent -0.65,-0.85 0.65,0.85, height 0.6
SOT563_DIODES [mm] "SOT563 (_M050_W1.2_), 6-Leads, Body 1.60x1.20, Pitch 0.5, HiDens (170926)"
  rrect25% 0.5x0.375 smd: 1(-0.85,0.5) 2(-0.85,0) 3(-0.85,-0.5) 4(0.85,-0.5) 5(0.85,0) 6(0.85,0.5)
  body extent -0.66,-0.85 0.65,0.85, height 0.6
SW_ALPS_SKRHAAE010 [mm] "Switch, ALPS / ALPINE (200615)"
  rrect20% 1.35x1 smd: 1(-3.575,1.425) 2(-3.575,0) 3(-3.575,-1.425) 4(3.575,1.425) 5(3.575,0) 6(3.575,-1.425)
  rrect20% 2x1.8 smd: 7(0,4.05) 8(0,-4.05)
  round 0 hole 0.75 unplated mask+0.102: M1(0,1.9)
  round 0 hole 1.05 unplated mask+0.102: M2(0,-1.9)
  body extent -3.74,-3.75 3.74,3.75, height 5
SW_CK_PTS810_SJM_250 [mm] "Switch C&K PTS810_SJM_250 (grey button) (180319)"
  rrect20% 1.05x0.65 smd: 1(-2.075,1.075) 2(2.075,1.075) 3(-2.075,-1.075) 4(2.075,-1.075)
  body extent -2.29,-1.6 2.29,1.6, height 2.5
TAB_V-CUT_L7.0_W2.4 [mm] "TAB V_CUT, Length 7.0, Width 2.4"
TDFN4_M050_1.6X1.2_EP_VISH [mm] "TDFN, 4-Leads, Body 1.60x1.20mm, IPC HiDens (180111)"
  rrect10% 0.55x0.3 smd: 1(-0.725,0.25) 2(-0.725,-0.25) 3(0.725,-0.25) 4(0.725,0.25)
  rrect10% 0.5x0.86 smd paste-0.05: 5(0,0)
  body extent -0.8,-0.6 0.8,0.6, height 0.61
TDFN8_M050_2.0X3.0_EP [mm] "TDFN8_M050_2.0x3.0_EP (170921)"
  rrect20% 0.75x0.3 smd: 1(-1.45,0.75) 2(-1.45,0.25) 3(-1.45,-0.25) 4(-1.45,-0.75) 5(1.45,-0.75) 6(1.45,-0.25) 7(1.45,0.25) 8(1.45,0.75)
  rrect10% 1.5x1.4 smd: 9(0,0)
  body extent -1.5,-1 1.5,1, height 1.01
TP_1.0_SMD [mm] "Test Point, 1.0 mm, SMD (170509)"
  round 1 smd paste-0.501: 1(0,0)
  body extent -0.5,-0.5 0.5,0.5, height 0.04
UQFN16_M040_1.8X2.6_TI_RSV [mm] "UQFN 16 Leads, Pitch 0.4, 1.9x2.6x0.5, TI: RSV (190816)"
  rrect20% 0.7x0.2 smd paste+0 mask+0.05: 1(-0.75,0.6)
  rrect20% 0.6x0.2 smd paste+0 mask+0.05: 2(-0.8,0.2) 3(-0.8,-0.2) 4(-0.8,-0.6) 9(0.8,-0.6) 10(0.8,-0.2) 11(0.8,0.2) 12(0.8,0.6)
  rrect20% 0.2x0.6 smd paste+0 mask+0.05: 5(-0.6,-1.2) 6(-0.2,-1.2) 7(0.2,-1.2) 8(0.6,-1.2) 13(0.6,1.2) 14(0.2,1.2) 15(-0.2,1.2) 16(-0.6,1.2)
  body extent -0.9,-1.3 0.9,1.3, height 0.56
VQFN24_M050_3.5X5.5_EP_TI_RHL [mm] "VQFN 24 Leads, Pitch 0.50 3.5x5.0x0.9, TI: RHL (171011)"
  rrect20% 0.28x0.99 smd: 1(-0.75,2.795) 12(-0.75,-2.795) 13(0.75,-2.795) 24(0.75,2.795)
  rrect20% 0.99x0.28 smd: 2(-1.795,2.25) 3(-1.795,1.75) 4(-1.795,1.25) 5(-1.795,0.75) 6(-1.795,0.25) 7(-1.795,-0.25) 8(-1.795,-0.75) 9(-1.795,-1.25) 10(-1.795,-1.75) 11(-1.795,-2.25) 14(1.795,-2.25) 15(1.795,-1.75) 16(1.795,-1.25) 17(1.795,-0.75) 18(1.795,-0.25) 19(1.795,0.25) 20(1.795,0.75) 21(1.795,1.25) 22(1.795,1.75) 23(1.795,2.25)
  rrect5% 2.05x4.05 smd: 25(0,0)
  Top Layer region: 0.39,-3.26 0.39,-2 -0.39,-2 -0.39,-3.26 -0.39,-3.266 -0.385,-3.277 -0.377,-3.285 -0.366,-3.29 -0.36,-3.29 -0.36,-3.29 -0.14,-3.29 -0.134,-3.29 -0.123,-3.285 -0.115,-3.277 -0.11,-3.266 -0.11,-3.26 -0.11,-3.26 -0.11,-2.32 -0.11,-2.316 -0.107,-2.309 -0.101,-2.303 -0.094,-2.3 -0.09,-2.3 -0.09,-2.3 0.09,-2.3 0.094,-2.3 0.101,-2.303 0.107,-2.309 0.11,-2.316 0.11,-2.32 0.11,-2.32 0.11,-3.26 0.11,-3.266 0.115,-3.277 0.123,-3.285 0.134,-3.29 0.14,-3.29 0.14,-3.29 0.36,-3.29 0.366,-3.29 0.377,-3.285 0.385,-3.277 0.39,-3.266 0.39,-3.26
  Top Layer region: -0.39,3.26 -0.39,2 0.39,2 0.39,3.26 0.39,3.266 0.385,3.277 0.377,3.285 0.366,3.29 0.36,3.29 0.36,3.29 0.14,3.29 0.134,3.29 0.123,3.285 0.115,3.277 0.11,3.266 0.11,3.26 0.11,3.26 0.11,2.32 0.11,2.316 0.107,2.309 0.101,2.303 0.094,2.3 0.09,2.3 0.09,2.3 -0.09,2.3 -0.094,2.3 -0.101,2.303 -0.107,2.309 -0.11,2.316 -0.11,2.32 -0.11,2.32 -0.11,3.26 -0.11,3.266 -0.115,3.277 -0.123,3.285 -0.134,3.29 -0.14,3.29 -0.14,3.29 -0.36,3.29 -0.366,3.29 -0.377,3.285 -0.385,3.277 -0.39,3.266 -0.39,3.26
  body extent -1.75,-2.75 1.75,2.75, height 1
VSSOP10_M050_W3.0_TI_DGS [mm] "VSSOP, 10-Leads, 3.0x3.0x(max1.1), Pitch 0.50mm, (TI: DGS) (190816)"
  rrect20% 1.45x0.3 smd: 1(-2.2,1) 2(-2.2,0.5) 3(-2.2,0) 4(-2.2,-0.5) 5(-2.2,-1) 6(2.2,-1) 7(2.2,-0.5) 8(2.2,0) 9(2.2,0.5) 10(2.2,1)
  body extent -1.5,-1.5 1.5,1.5, height 1.1
WCON_1125B-1210_HOR_PEG-2X10 [mm] "WCON 2x10 header (201021)"
  rrect50% 1.27x3.175 smd: 1(-1.27,4.24) 2(-1.27,8.43) 3(1.27,4.24) 4(1.27,8.43) 5(3.81,4.24) 6(3.81,8.43) 7(6.35,4.24) 8(6.35,8.43) 9(8.89,4.24) 10(8.89,8.43) 11(11.43,4.24) 12(11.43,8.43) 13(13.97,4.24) 14(13.97,8.43) 15(16.51,4.24) 16(16.51,8.43) 17(19.05,4.24) 18(19.05,8.43) 19(21.59,4.24) 20(21.59,8.43)
  round 0 hole 1.9 unplated paste+0.91 mask+0.1: M1(0,0) M2(20.32,0)
  body extent -2.54,-7.11 22.86,9.15, height 6.1
WCON_3132_HDR_M127_SMD-2X10 [mm] "WCON_3132_HDR_M127_SMD-2X10 (210215)"
  rrect50% 0.74x2.4 smd: 1(-5.715,-1.95) 2(-5.715,1.95) 3(-4.445,-1.95) 4(-4.445,1.95) 5(-3.175,-1.95) 6(-3.175,1.95) 7(-1.905,-1.95) 8(-1.905,1.95) 9(-0.635,-1.95) 10(-0.635,1.95) 11(0.635,-1.95) 12(0.635,1.95) 13(1.905,-1.95) 14(1.905,1.95) 15(3.175,-1.95) 16(3.175,1.95) 17(4.445,-1.95) 18(4.445,1.95) 19(5.715,-1.95) 20(5.715,1.95)
  body extent -6.35,-4.53 6.35,2.84, height 6.58
WSON8_M050_3.0X2.5_EP_TI_NGM [mm] "WSON8, Pitch 0.5, 3.0x2.5x0.8 EP TI: NGM (181205)"
  rrect20% 0.5x0.25 smd mask+0.051: 1(-1.15,0.75) 2(-1.15,0.25) 3(-1.15,-0.25) 4(-1.15,-0.75) 5(1.15,-0.75) 6(1.15,-0.25) 7(1.15,0.25) 8(1.15,0.75)
  rrect10% 1.2x1.5 smd mask+0.051: 9(0,0)
  body extent -1.5,-1.25 1.5,1.25, height 0.8
X2-DFN1006-2 [mm] "Diodes case X2-DFN1006-2 part DESD5V0S1BLD (201012)"
  rrect20% 0.4x0.7 smd mask+0.04: 1(-0.35,0) 2(0.35,0)
  body extent -0.5,-0.3 0.5,0.3, height 0.41
X2-DFN1010-6_M035_DIODES [mm] "X2-DFN1010-6 Pitch 0.35 1.0x1.0x0.4, Diodes Inc (181025)"
  rrect20% 0.55x0.2 smd mask+0.04: 1(-0.35,0.35) 2(-0.35,0) 3(-0.35,-0.35) 4(0.35,-0.35) 5(0.35,0) 6(0.35,0.35)
  body extent -0.5,-0.5 0.5,0.5, height 0.41
X2-DFN2015-3_DIODES [mm] "X2-DFN2015-3 DIODES (181204)"
  rrect10% 0.5x0.31 smd mask+0.07: 1(-0.9,0.5) 2(-0.9,-0.5)
  rrect10% 0.75x0.31 smd mask+0.07: 3(0.775,0)
  Top Layer region: 0.5,0.55 0.5,-0.55 0.5,-0.57 0.485,-0.607 0.457,-0.635 0.42,-0.65 0.4,-0.65 0.4,-0.65 -0.4,-0.65 -0.42,-0.65 -0.457,-0.635 -0.485,-0.607 -0.5,-0.57 -0.5,-0.55 -0.5,-0.55 -0.5,0.55 -0.5,0.57 -0.485,0.607 -0.457,0.635 -0.42,0.65 -0.4,0.65 -0.4,0.65 0.4,0.65 0.42,0.65 0.457,0.635 0.485,0.607 0.5,0.57 0.5,0.55
  body extent -1.04,-0.79 1.04,0.79, height 0.4
X_KDS_DSX211SH_2.0X1.65-4 [mm] "X_KDS_DSX211SH_2.0X1.65-4 (190312)"
  rrect20% 0.9x0.8 smd: 1(-0.7,-0.55) 2(0.7,-0.55) 3(0.7,0.55) 4(-0.7,0.55)
  body extent -1.07,-0.87 1.07,0.87, height 0.5

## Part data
LED900: library part Yellow
LED901: library part Blue

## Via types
v1: diameter 0.508, hole 0.25, Top Layer to Bottom Layer, tented both sides, 1129 vias

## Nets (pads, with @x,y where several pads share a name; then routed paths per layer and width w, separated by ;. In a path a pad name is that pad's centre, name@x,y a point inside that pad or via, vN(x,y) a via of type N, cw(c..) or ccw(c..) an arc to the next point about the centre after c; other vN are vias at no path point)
3V3: C607.1 C807.1 C808.1 C860.1 C862.1 C864.1 C866.1 C868.1 C907.1 C908.1 C909.1 C910.1 C911.1 C914.1 C921.1 C922.1 C924.1 C925.1 C926.1 C927.1 C951.1 D807.1 J101.31 J101.32 J102.31 J102.32 L704.1 L900.1 P101.20 P801.3 R142.2 R601.2 R838.2 R840.2 R903.1 R906.2 R907.1 R908.1 R909.1 R912.1 R919.1 R920.1 R982.1 TPJ600.1 TPJ950.1 U600.1 U600.4 U803.6 U807.6 U808.1 U860.1 U861.1 U862.1 U863.1 U900.C6 U900.C9 U900.G3 U900.H11 U900.J11 U900.K3 U900.L4 U900.L7 U901.8 U902.A1 U902.E3 U910.2 | length 113.1
  Top Layer w0.2: R903.1@14.925,49.05 15.904,49.05 16.129,48.825 v1(16.175,48.825) ; U600.1@17.282,55.897 17.282,56.047 ; v1(17.7,49.05) R919.1@18.3,49.05 ; v1(17.7,49.75) R920.1@18.3,49.75 ; R912.1@20.8,46.8 v1(21.4,46.8) ; C924.1@41,43.925 41,44.325 41.125,44.45 41.35,44.45 41.55,44.25 C925.1@41.55,43.925 ; U900.H11@44.6,45 U900.J11@44.6,45.5 44.8,45.5 44.942,45.358 v1(44.974,45.358) ; U900.C9@45.6,42.5 45.6,43.025 v1(45.7,43.125) ; v1(46.525,46) 46.525,46.425 U900.L7@46.6,46.5 ; U900.C6@47.1,42.5 47.1,42.925 v1@47.175,43 ; U900.L4@48.1,46.5 48.1,46.35 48.25,46.2 48.25,46.15 v1(48.225,46.125) 48.475,46.125 U900.K3@48.6,46 ; v1(48.225,44.625) 48.35,44.5 U900.G3@48.6,44.5 ; v1(50.441,44.887) 50.472,44.919 50.894,44.919 C911.1@50.925,44.95 ; U860.1@52.3,47.65 52.925,47.65 C862.1@53.05,47.775 53.05,47.204 v1(53.047,47.201) ; v1@52.9,36.1 53.025,35.975 C914.1@53.025,35.6 53.05,35.575 U902.A1@53.05,34.7 ; U901.8@53.475,50.7 53.57,50.7 53.82,50.95 54.3,50.95 54.412,50.838 54.662,50.838 C951.1@54.722,50.778 54.722,51.238 54.55,51.411 v1@54.55,51.435 ; U902.E3@53.75,33.9 53.75,33.897 54.145,33.502 v1(54.145,33.455) ; R906.2@54.45,35.3 55.025,35.3 v1(55.1,35.225) ; v1(54.498,51.502) 54.498,51.487 v1@54.55,51.435 ; v1@54.55,51.475 v1@54.55,51.435 ; v1@54.625,51.36 v1@54.55,51.435 ; R908.1@55.139,49.175 55.192,49.228 55.403,49.228 55.696,49.521 55.696,49.896 v1(55.7,49.9) ; R909.1@55.25,50.225 55.284,50.191 55.53,50.191 55.725,49.996 v1@55.725,49.9 ; v1(61.866,36.253) 61.858,36.261 61.858,37.092 C860.1@61.85,37.1 61.85,37.15 62.1,37.4 U862.1@62.1,37.85 ; C808.1@62.625,46.85 62.625,47.225 v1(62.75,47.35) ; C864.1@66.65,39.625 67.175,39.625 U861.1@67.25,39.55 ; C866.1@67.15,32.725 67.15,32.925 67.35,33.125 U863.1@67.35,33.45
  Top Layer w0.203: U803.6@70.725,47.775 71.525,47.775 C807.1@71.575,47.825 71.575,48.25 v1(71.675,48.35) ; U807.6@71.763,25.825 72.365,25.825 C868.1@72.376,25.814 72.382,25.82 72.845,25.82 v1(72.875,25.85)
  Top Layer w0.25: 17.282,54.247 U600.4@17.282,54.397
  Top Layer w0.3: 17.282,56.047 v1(17.282,56.422) ; v1(19.757,53.622) 19.77,53.61 20.372,53.61 R601.2@20.382,53.597 R601.2@20.382,53.597 ; v1(39.312,44.865) 39.352,44.825 39.875,44.825 40.25,44.45 v1(41,44.45) v1@41.125,44.45 ; v1(40.37,21.085) 40.37,21.111 40.756,21.497 R142.2@40.756,22.683 ; v1(44.95,36) C922.1@44.95,35.5 44.975,35.525 U910.2@46.225,35.525 47.025,35.525 47.35,35.85 47.35,36.925 C921.1@46.825,37.45 ; C927.1@45.325,39.675 v1(45.325,40.175) ; R982.1@45.954,37.831 45.954,37.821 45.964,37.811 46.189,37.811 46.25,37.75 46.65,37.75 C921.1@46.9,37.5 ; v1(46.957,40.35) 47.004,40.304 46.965,40.265 46.965,39.685 C926.1@46.975,39.675 ; C910.1@47.634,49.333 47.637,49.333 47.647,49.323 47.647,48.312 v1(47.661,48.299) ; C908.1@48.925,48.8 48.925,49.225 v1(49.025,49.325) ; v1(51.748,43.738) 51.788,43.699 51.926,43.699 52.225,43.4 52.225,43.234 52.235,43.224 C909.1@52.255,43.224 ; R907.1@55.265,49.726 55.275,49.736 55.479,49.736 55.604,49.86 v1@55.665,49.86 ; v1(61.05,29) 61.052,28.998 61.599,28.998 R838.2@61.601,28.996 ; C808.1@62.625,46.85 62.65,46.825 U808.1@62.65,45.845 ; v1(65,31.4) 65.35,31.05 R840.2@65.4,31.05 ; v1(66.05,39.25) 66.05,39.375 66.3,39.625 C864.1@66.65,39.625 ; v1(67,32.2) 67,32.575 C866.1@67.15,32.725 ; D807.1@97.4,52 97.4,51.35 v1(97.525,51.225)
  Top Layer w0.305: v1(23.45,52.175) 23.463,52.162 23.463,51.613 L704.1@23.475,51.6
  Top Layer w0.5: v1(17.032,52.347) 17.032,52.747 C607.1@17.382,53.097 ; 17.282,54.247 17.282,53.197 C607.1@17.382,53.097 ; 17.5,53.8 17.5,53.215 C607.1@17.382,53.097 ; v1(17.657,52.322) 17.657,52.822 C607.1@17.382,53.097 ; L900.1@37.725,50.035 37.81,50.12 37.81,50.592 37.829,50.61 v1(37.829,50.612)
  Top Layer w0.635: v1(99.825,56.4) 100.445,57.02 P801.3@100.445,57.841 ; v1(101.875,41.675) 102.12,41.43 P101.20@104.57,41.43
  Signal Layer 3 w0.3: 17.25,53.225 17.85,52.625 18.175,52.625 ; v1(17.657,52.322) 17.697,52.362 17.912,52.362 18.175,52.625 ; 18.613,53.063 18.175,52.625 ; 18.687,53.138 19.172,53.622 v1(19.757,53.622) ; v1(28.372,21.181) 28.411,21.142 28.558,21.142 28.576,21.124 40.331,21.124 v1(40.37,21.085)
  Signal Layer 3 w1: v1@17.03,52.345 17.053,52.322 v1(17.657,52.322) ; 17.191,52.788 v1@17.191,56.422
  Signal Layer 4 w0.3: v1(25.425,17.05) 28.375,20 v1@28.375,21.2
  Signal Layer 4 w0.635: v1(97.525,51.225) 97.525,52.8 99.825,55.1 v1(99.825,56.4)
  Signal Layer 4 w1.3: v1(62.95,27.9) v1(62.95,27.25) 62.95,26.775 65.375,24.35 65.375,12.325 69.05,8.65 J101.32@69.05,5.802 J101.31@69.05,3.262
  Bottom Layer w0.3: TPJ600.1@14.353,32.302 15.077,32.302 v1(15.275,32.5) ; TPJ950.1@24.452,17.1 24.502,17.05 v1(25.425,17.05)
  other v1: 53.025,36.1 47.35,36.6 101.9,42.575 47.15,43
3V6_SW: C608.1 L702.1 Q601.1 R639.2 U603.B1 | length 47.3
  Top Layer w0.2: U603.B1@44.55,32.65 44.55,33.075
  Top Layer w0.3: v1@22.4,22.95 Q601.1@22.4,24.575 ; v1(48.815,33.427) 48.84,33.402 48.84,32.81 R639.2@48.85,32.8
  Top Layer w0.5: L702.1@43.765,34.05 43.965,33.85 v1(44.55,33.85) 44.55,33.075 45.225,33.075 C608.1@45.3,33
  Signal Layer 3 w0.4: v1(44.55,33.85) 44.571,33.871 45.3,33.871 45.604,34.175 46.05,34.175 47.025,33.2 47.725,33.2 47.952,33.427 v1(48.815,33.427)
  Signal Layer 3 w0.5: v1(22.375,22.95) 25.7,19.625 v1(43.3,19.625)
  Signal Layer 4 w0.5: v1(43.3,19.625) 44.8,21.125 44.8,33.598 44.55,33.848 v1(44.55,33.85)
3V6_SW_SENSE: C641.1 R639.1 R640.2 TP923.1 U910.4 | length 7.4
  Top Layer w0.1: v1(45.8,33.5) 45.6,33.5 45.275,33.825 45.275,34.2 45.6,34.525 U910.4@46.225,34.525 47.175,34.525 47.75,33.95 C641.1@47.75,32.775 47.775,32.8 R640.2@48.3,32.8 48.85,32.25 R639.1@48.85,32.2
  Bottom Layer w0.1: v1(45.8,33.5) TP923.1@46.5,34.2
